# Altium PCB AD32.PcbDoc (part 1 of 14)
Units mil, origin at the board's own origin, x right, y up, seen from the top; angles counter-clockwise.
Board outline 7007.87 x 4368.85 mil, 12 copper layers (Top Layer, Int1 (GND), Int2 (AVDD), Int3 (DVDD), Int4 (GND), Int5 (ST), Int6 (SB), Int8 (AGND), Int7 (AVCC), Int9 (VCCA), Int10 (GND), Bottom Layer), stack 60.136 mil thick; 1350 components, 880 nets, 4712 pads, 2835 vias.
Unrouted connection lines stored in the file: 19.
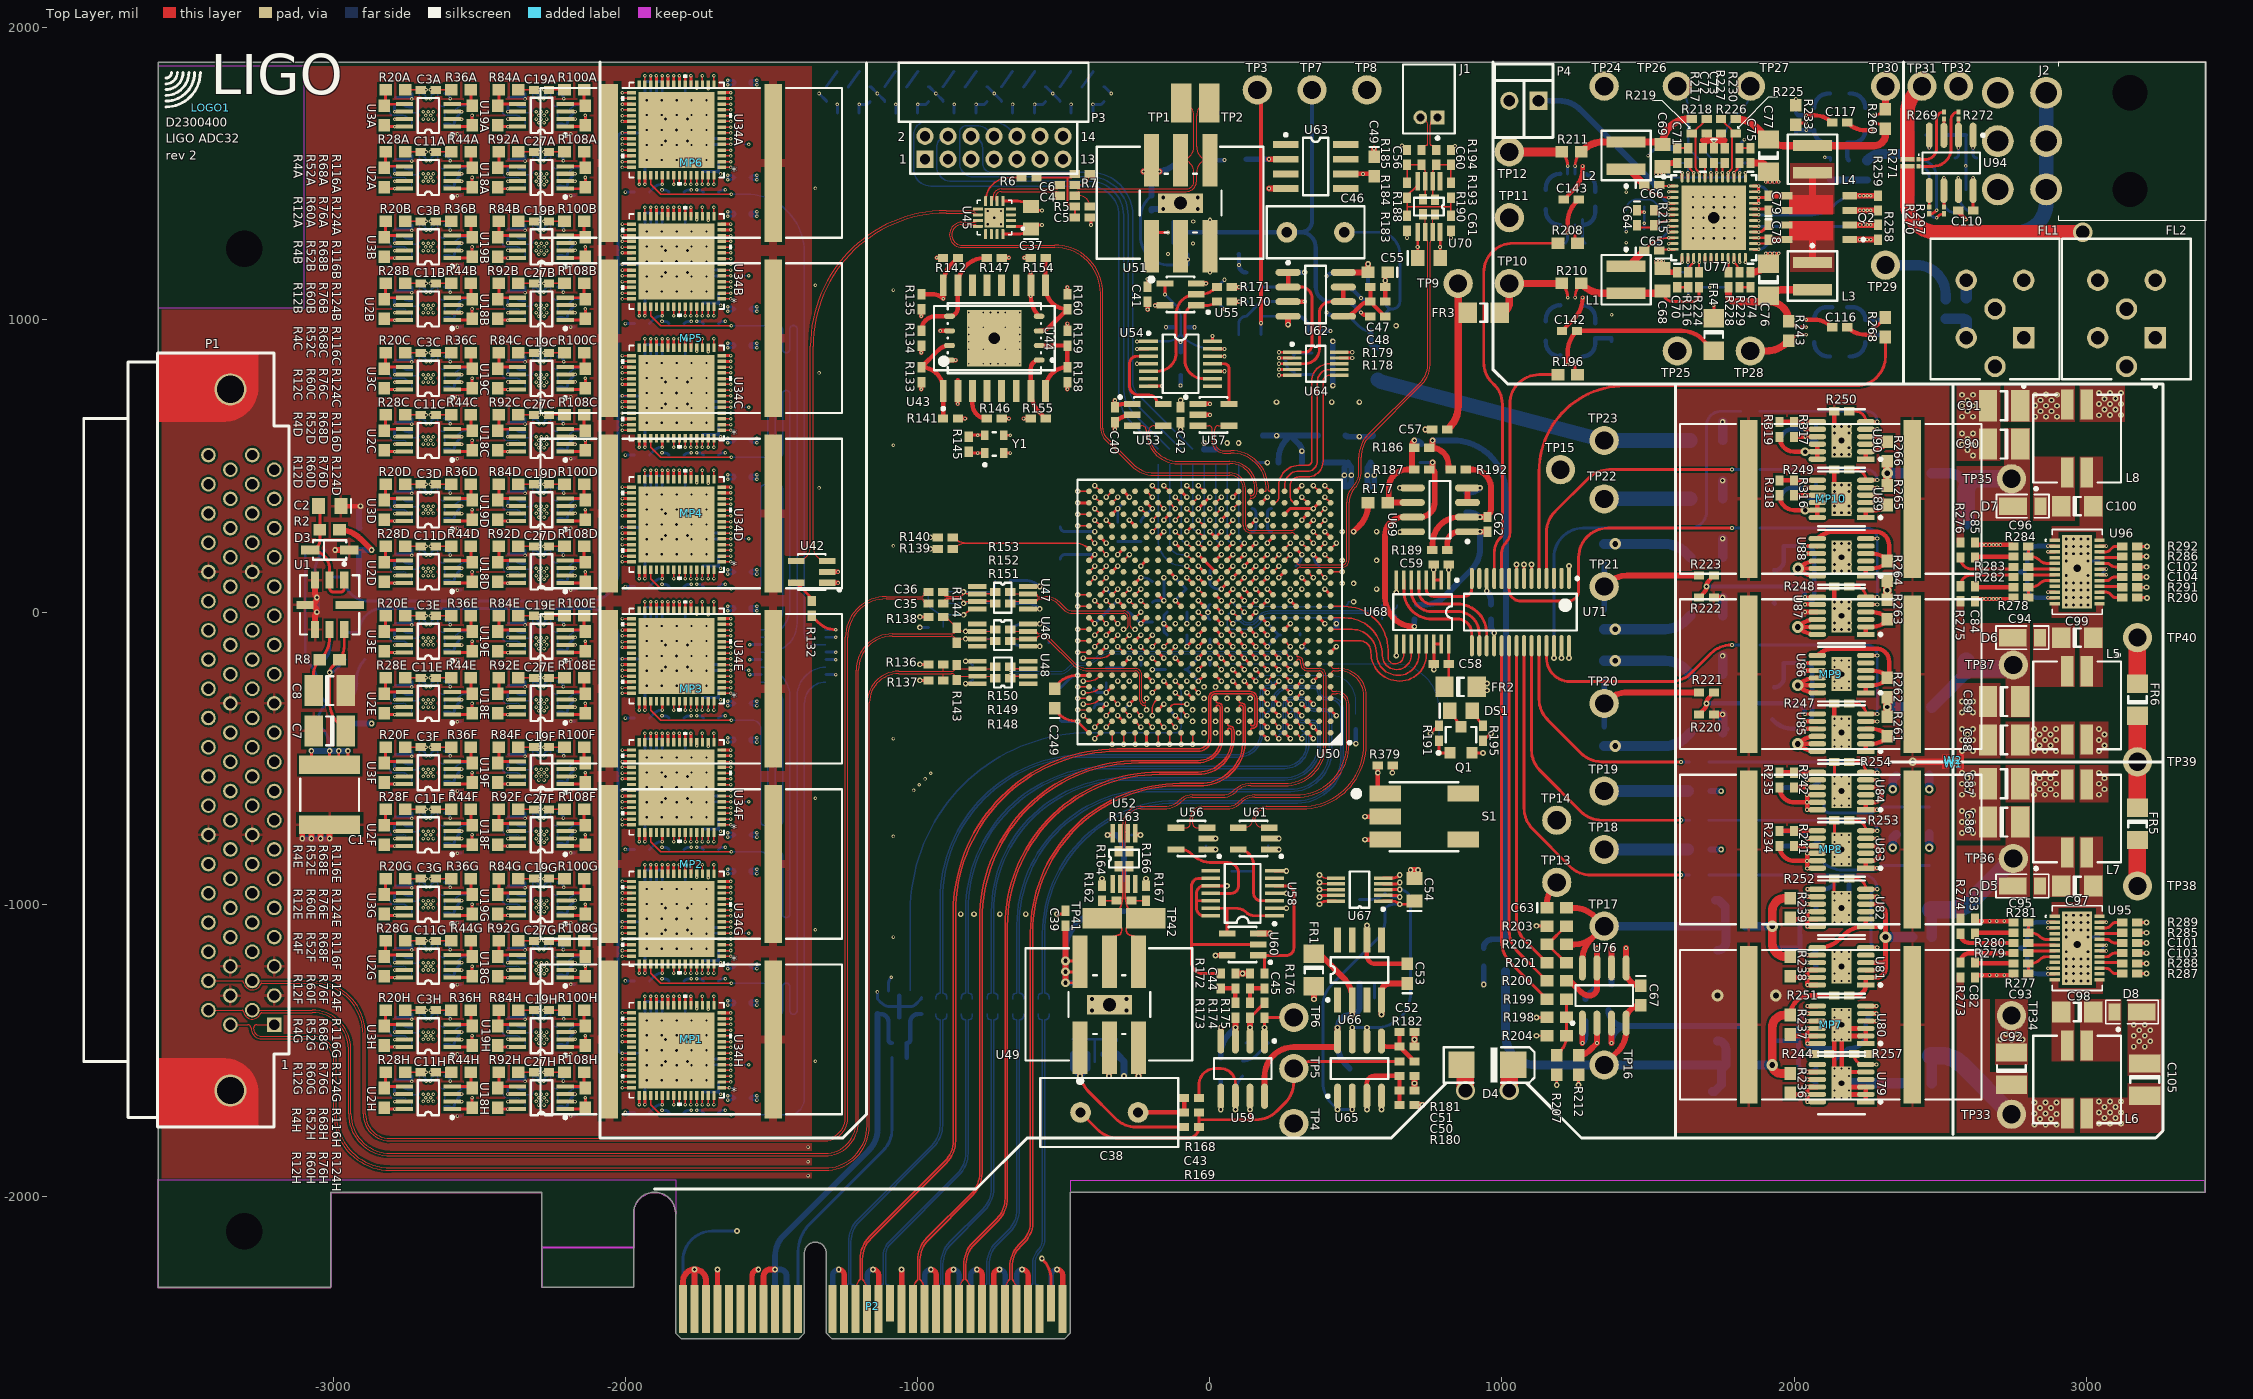
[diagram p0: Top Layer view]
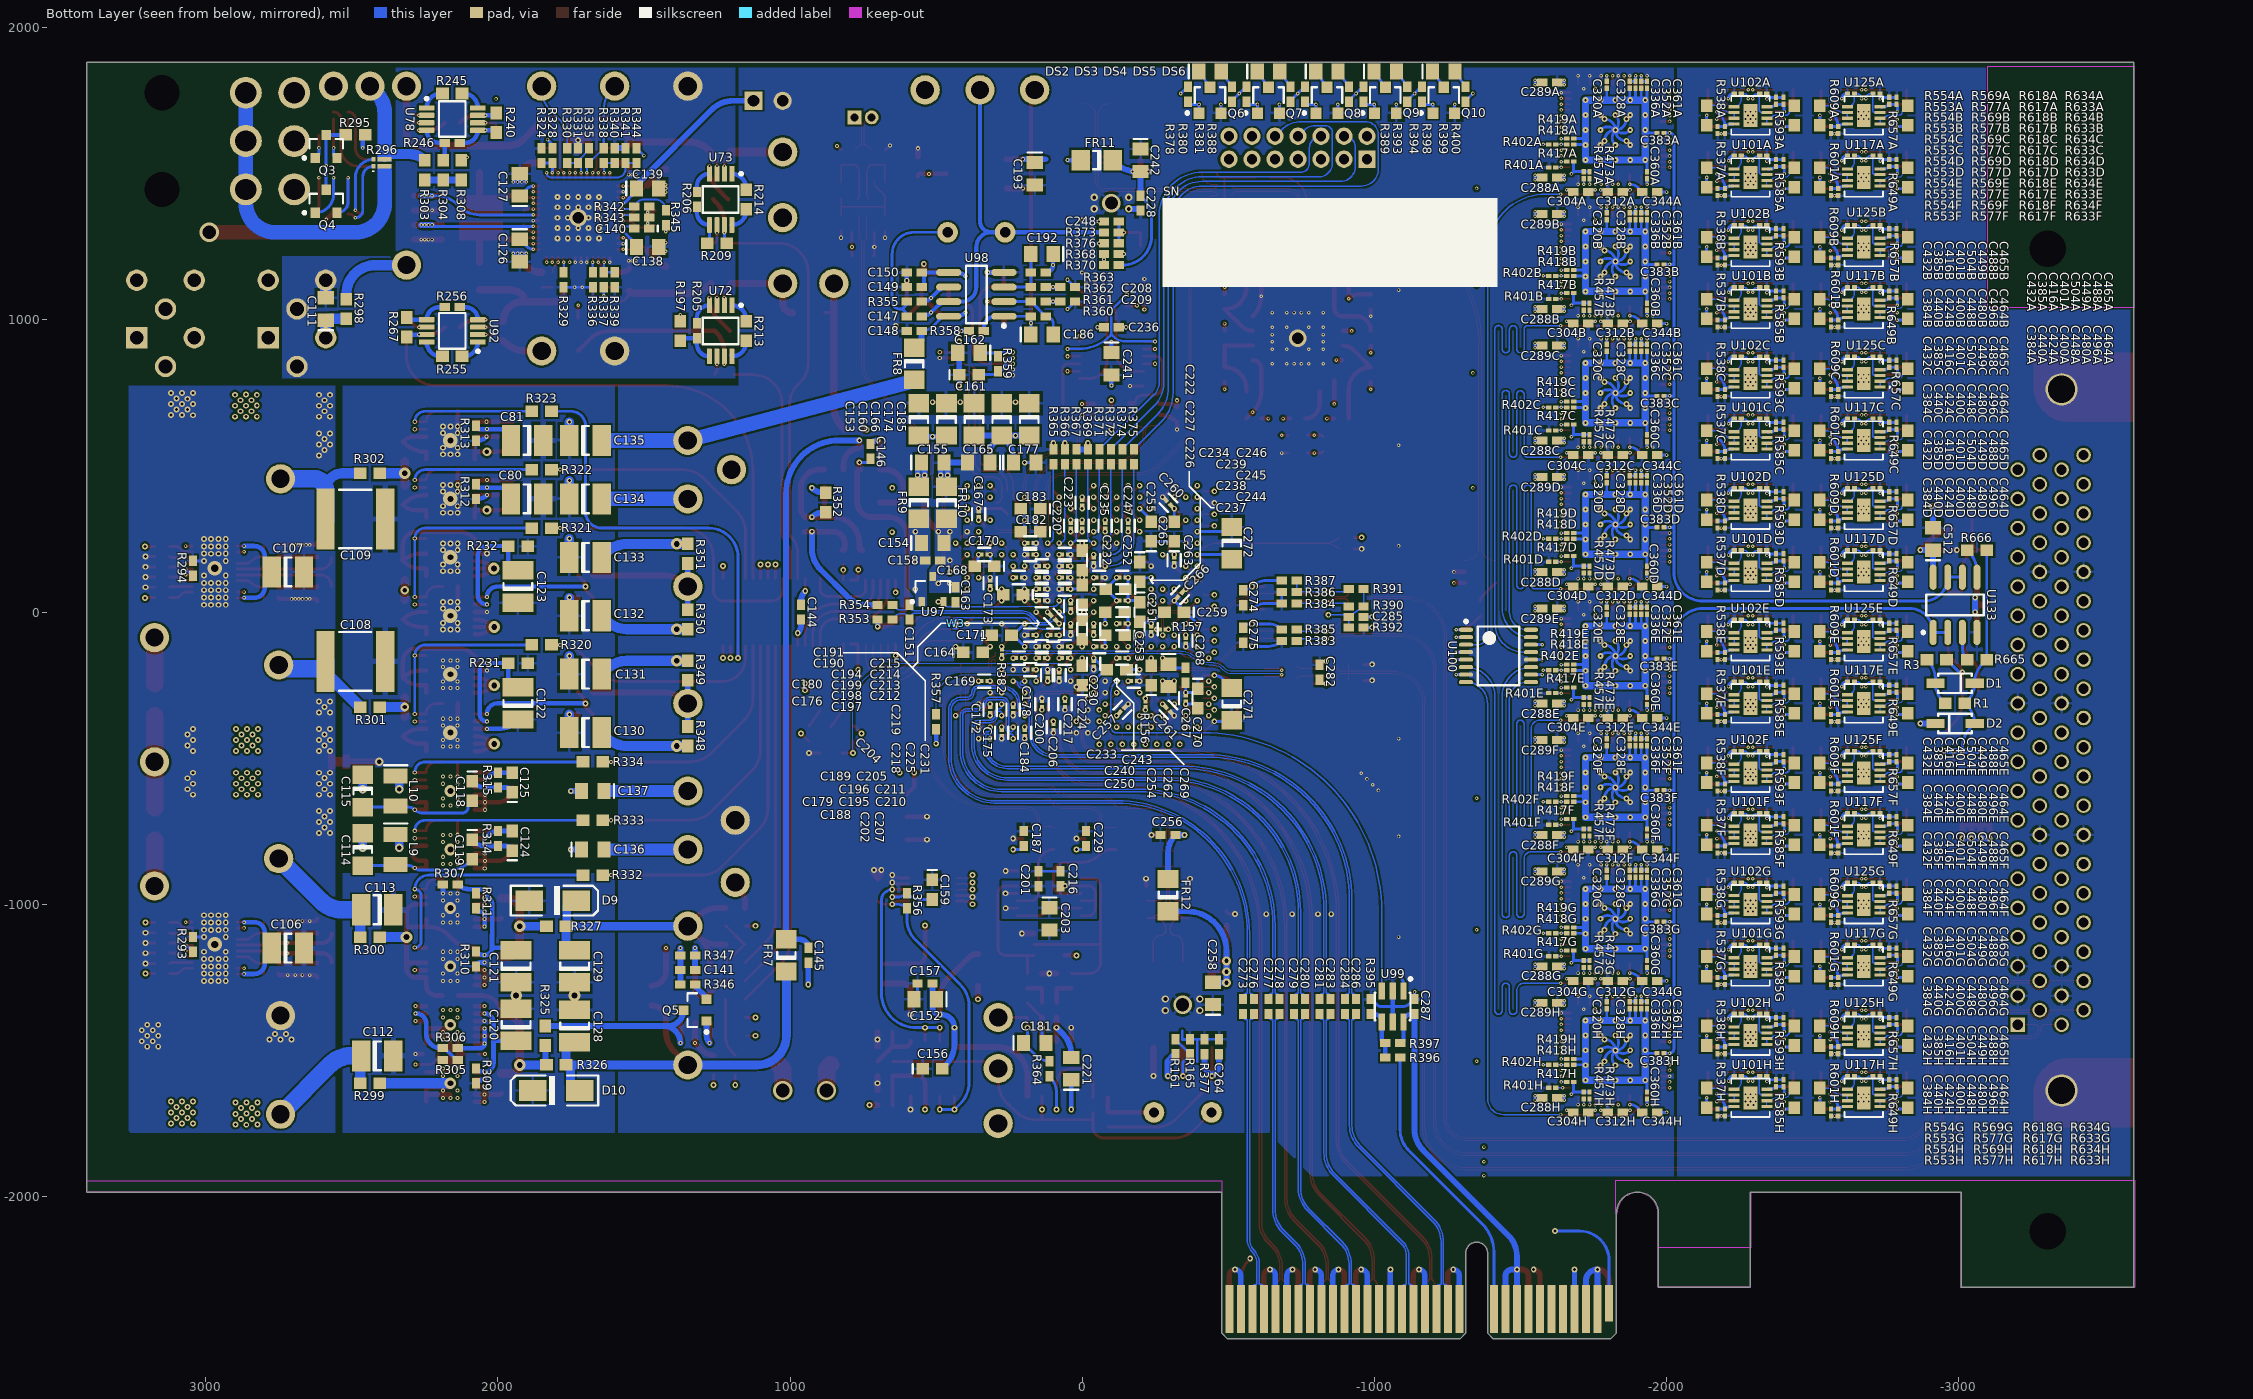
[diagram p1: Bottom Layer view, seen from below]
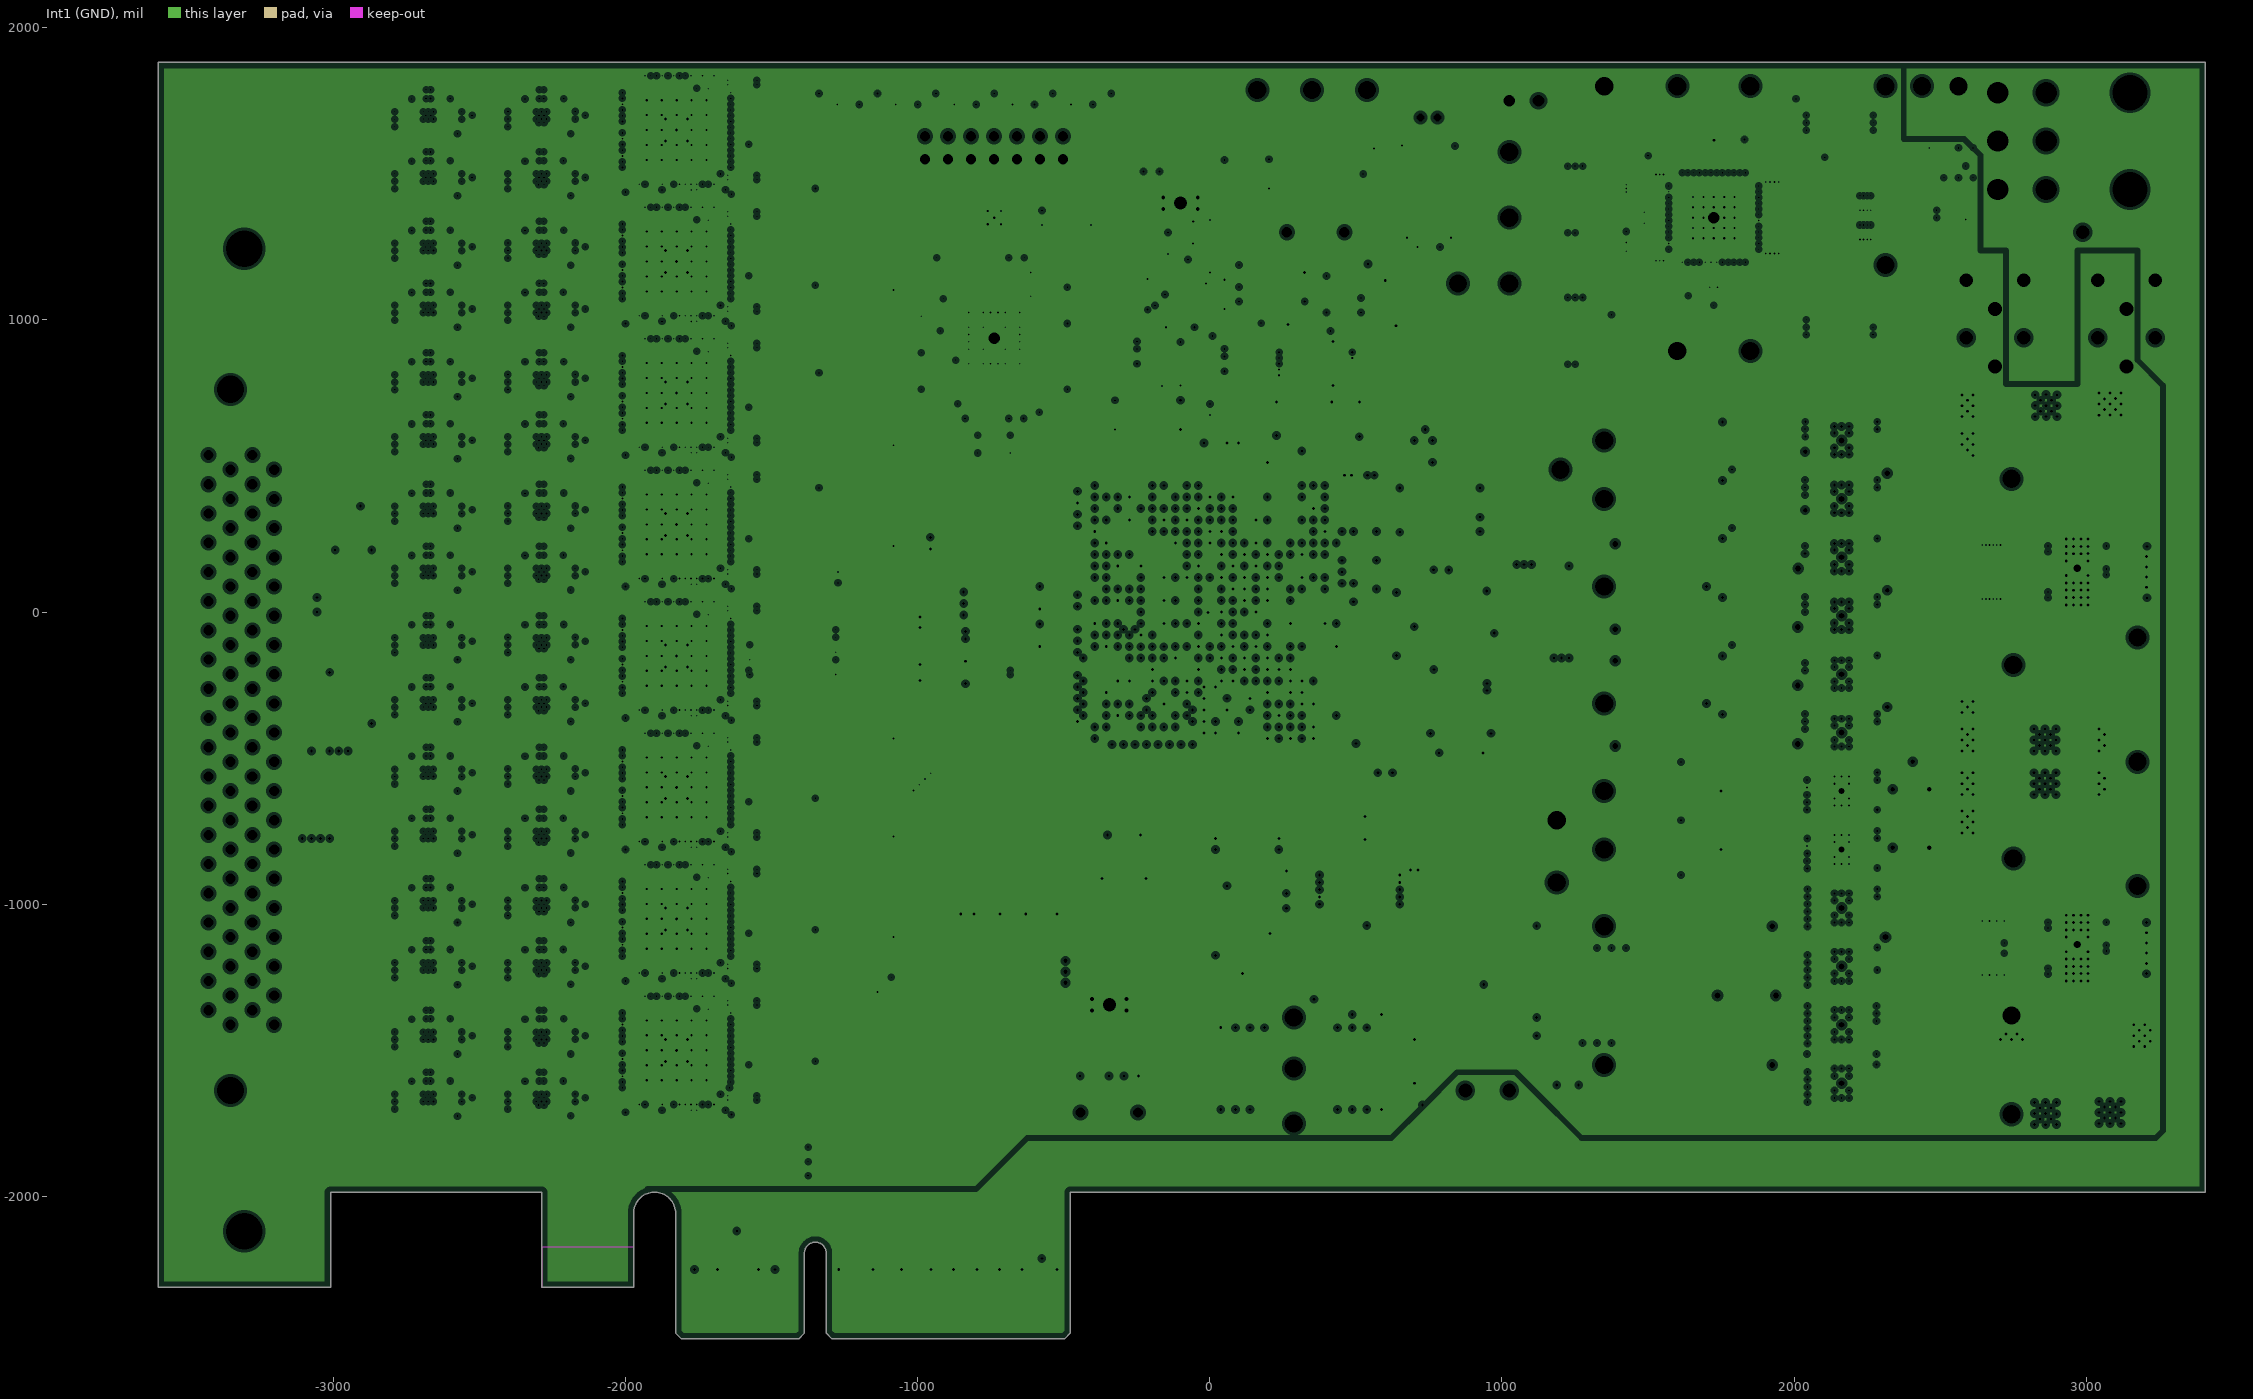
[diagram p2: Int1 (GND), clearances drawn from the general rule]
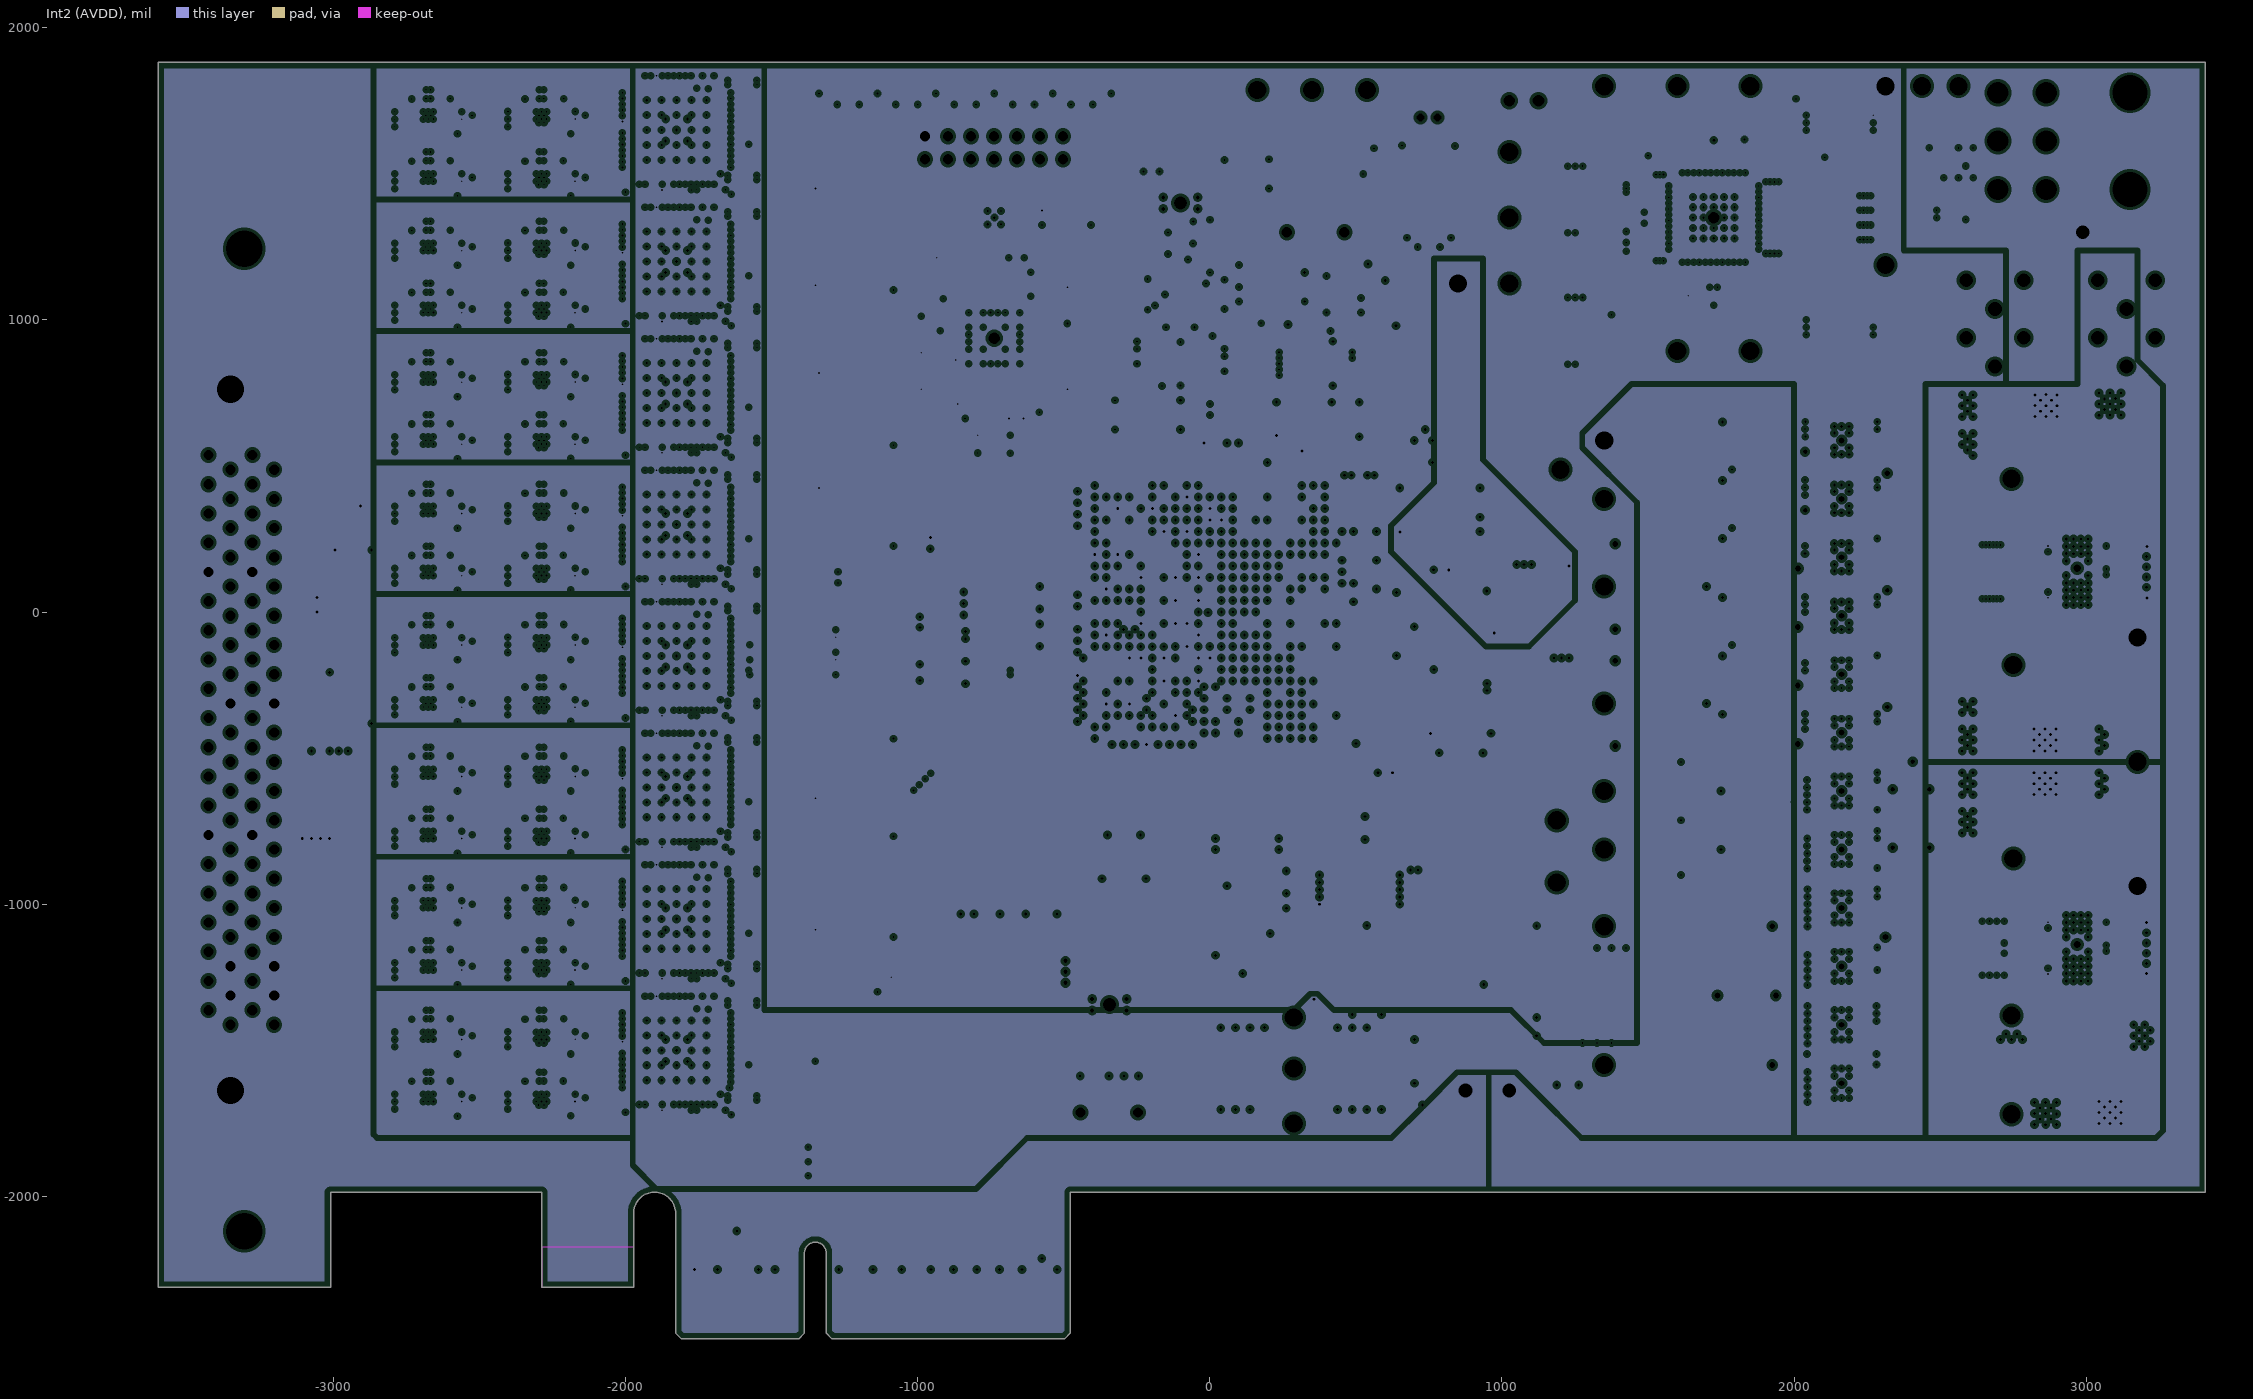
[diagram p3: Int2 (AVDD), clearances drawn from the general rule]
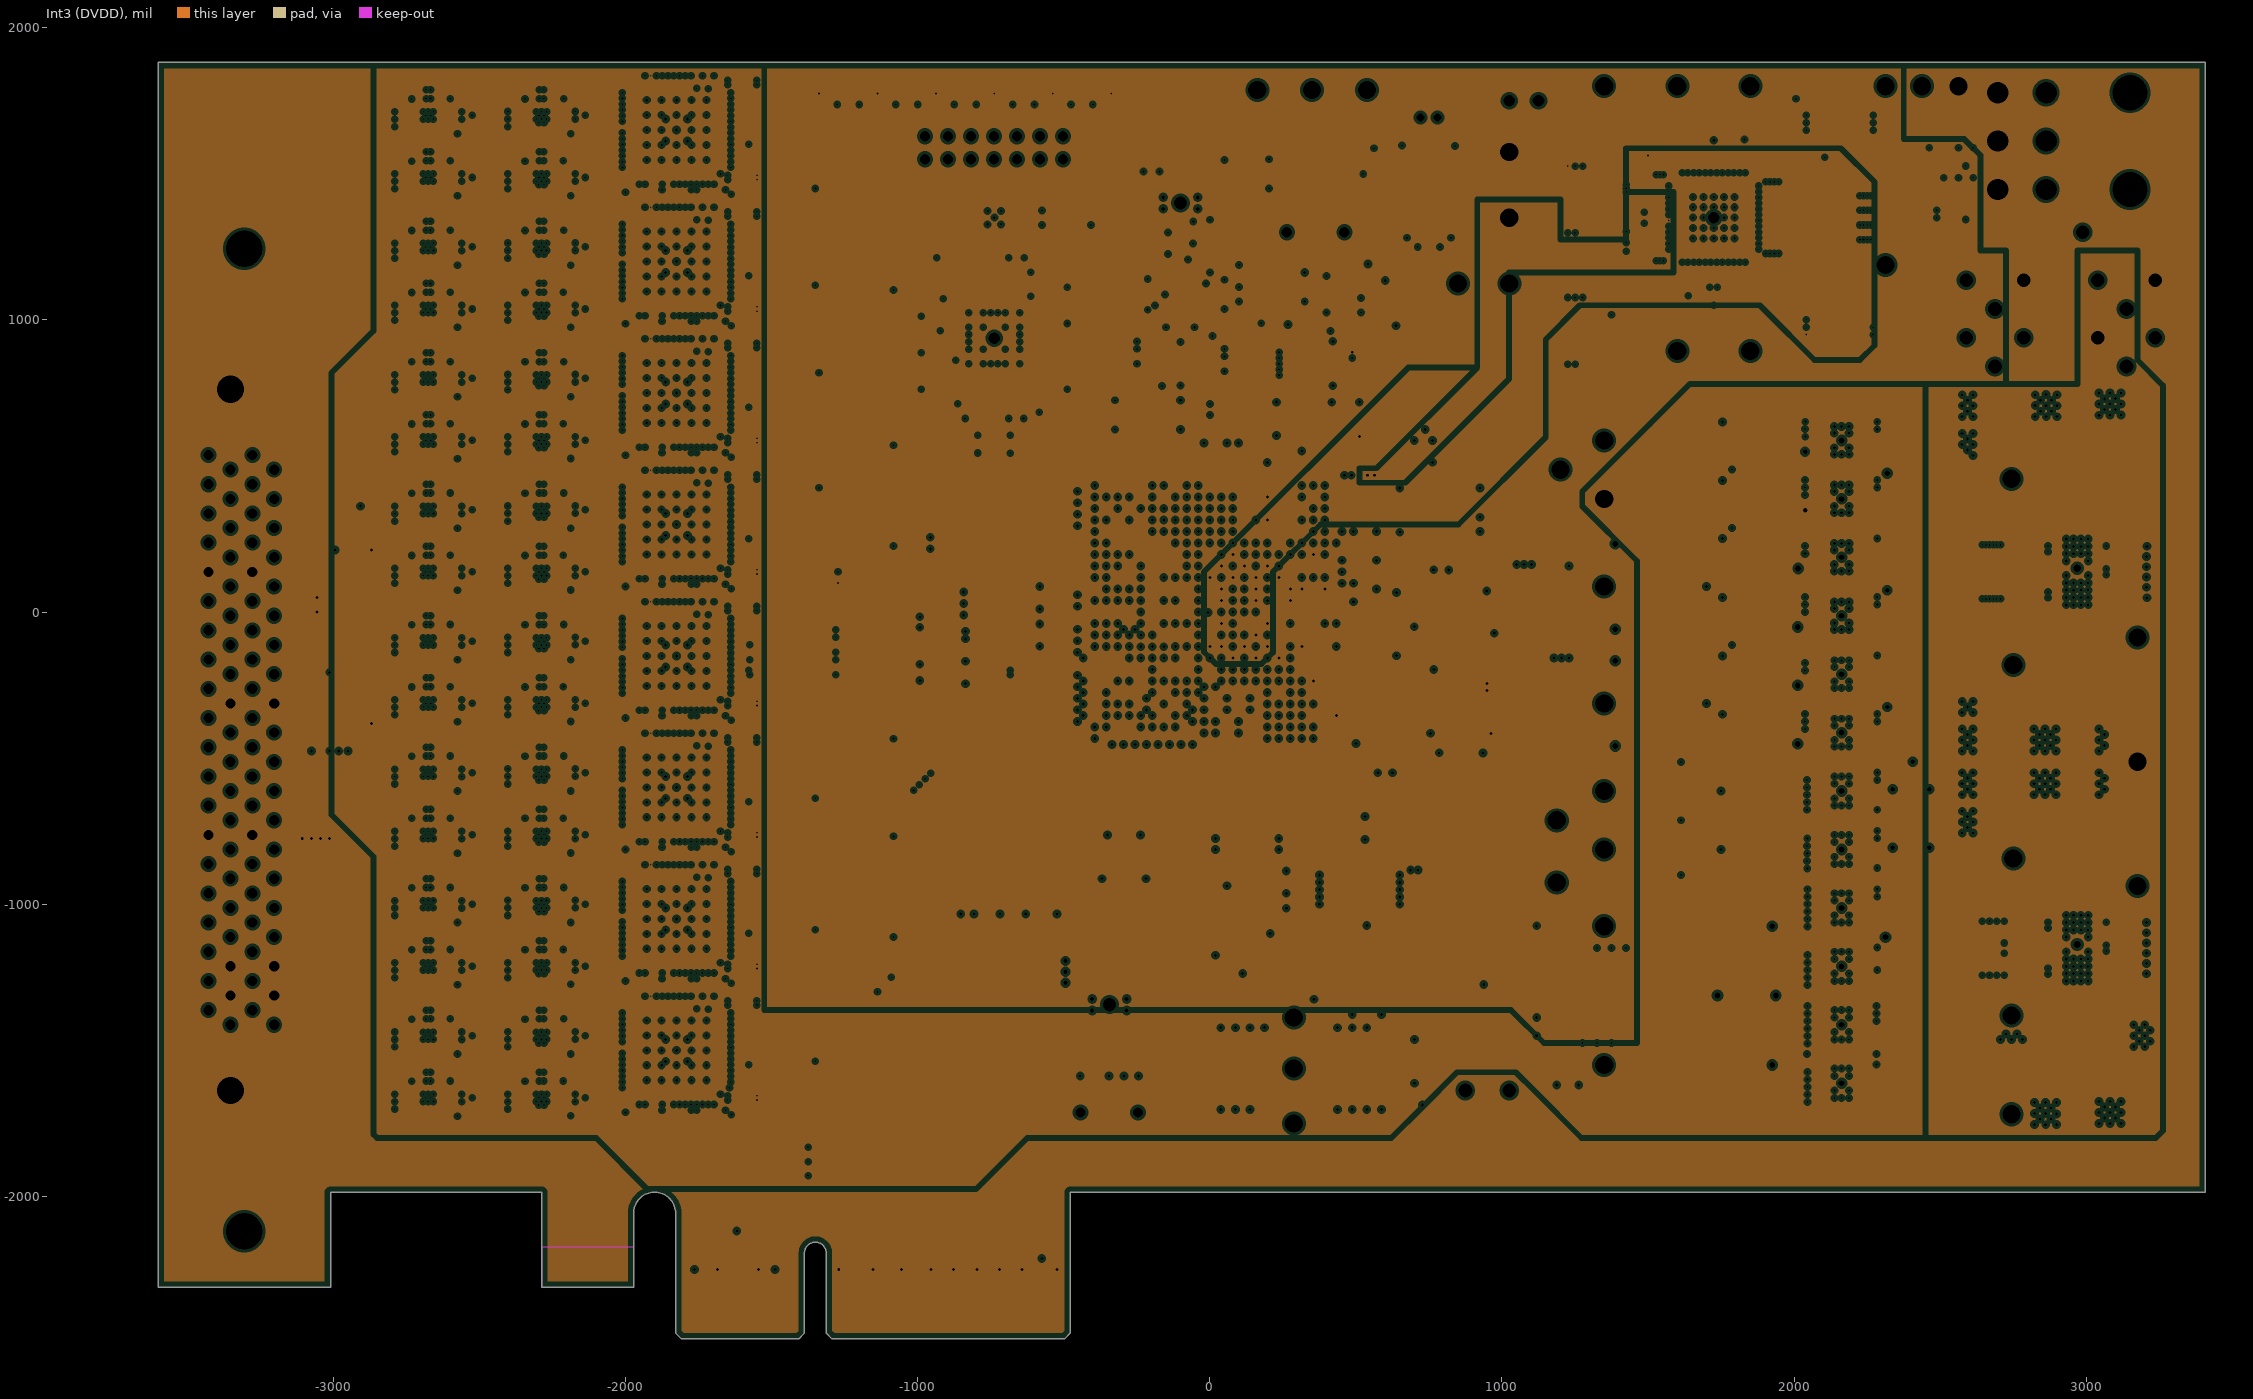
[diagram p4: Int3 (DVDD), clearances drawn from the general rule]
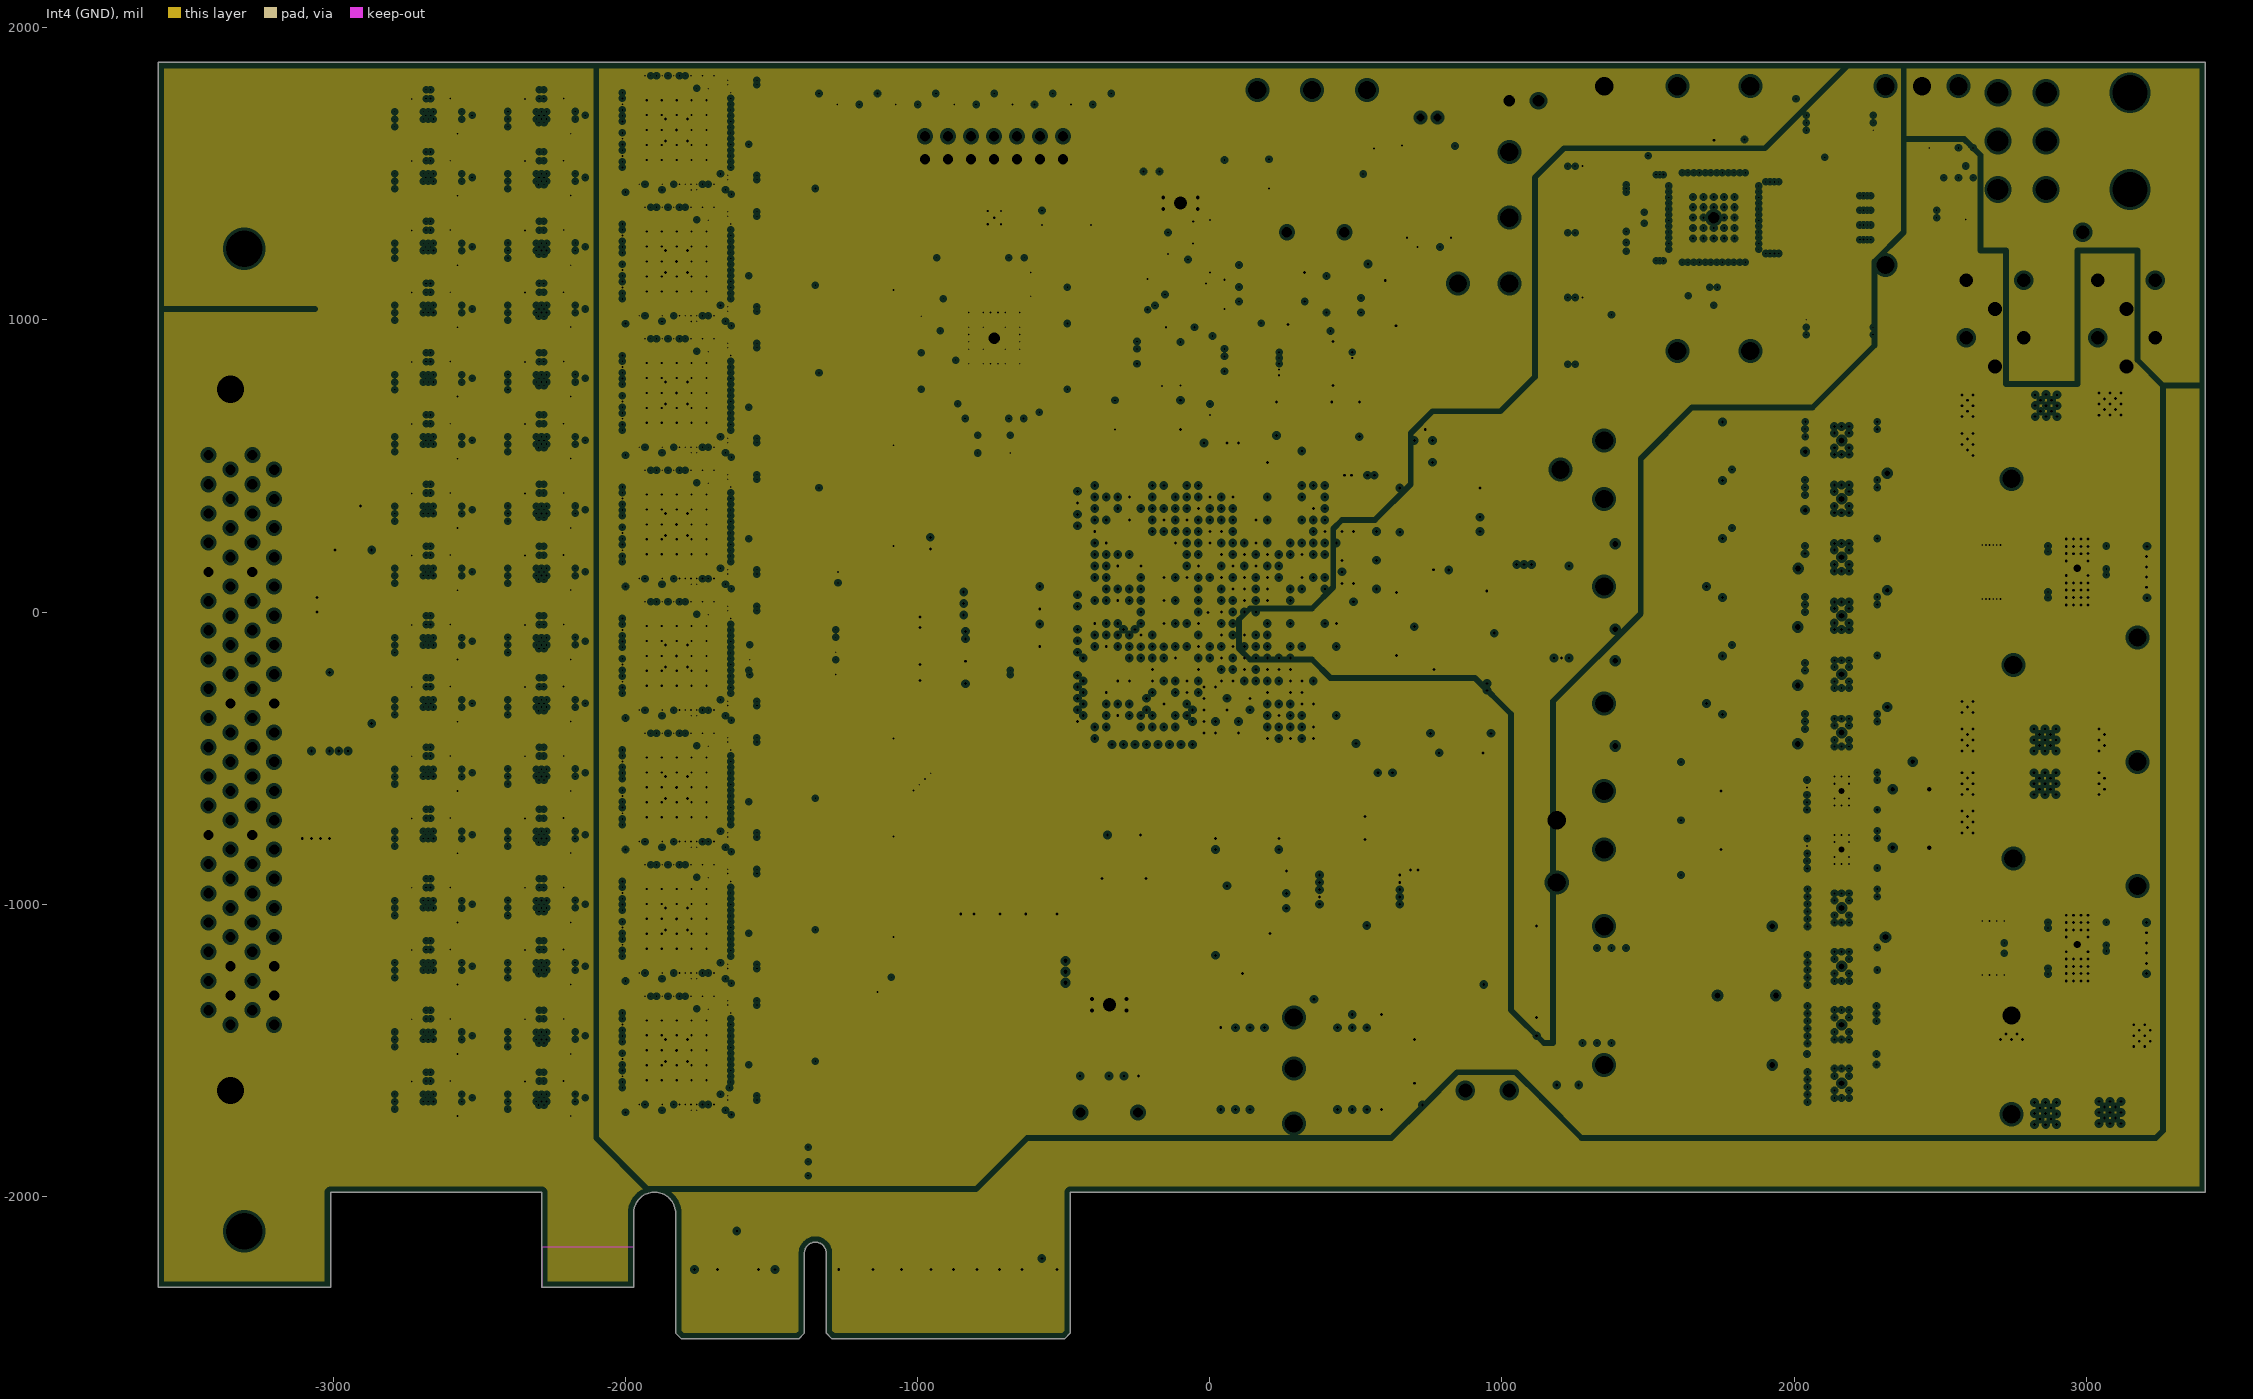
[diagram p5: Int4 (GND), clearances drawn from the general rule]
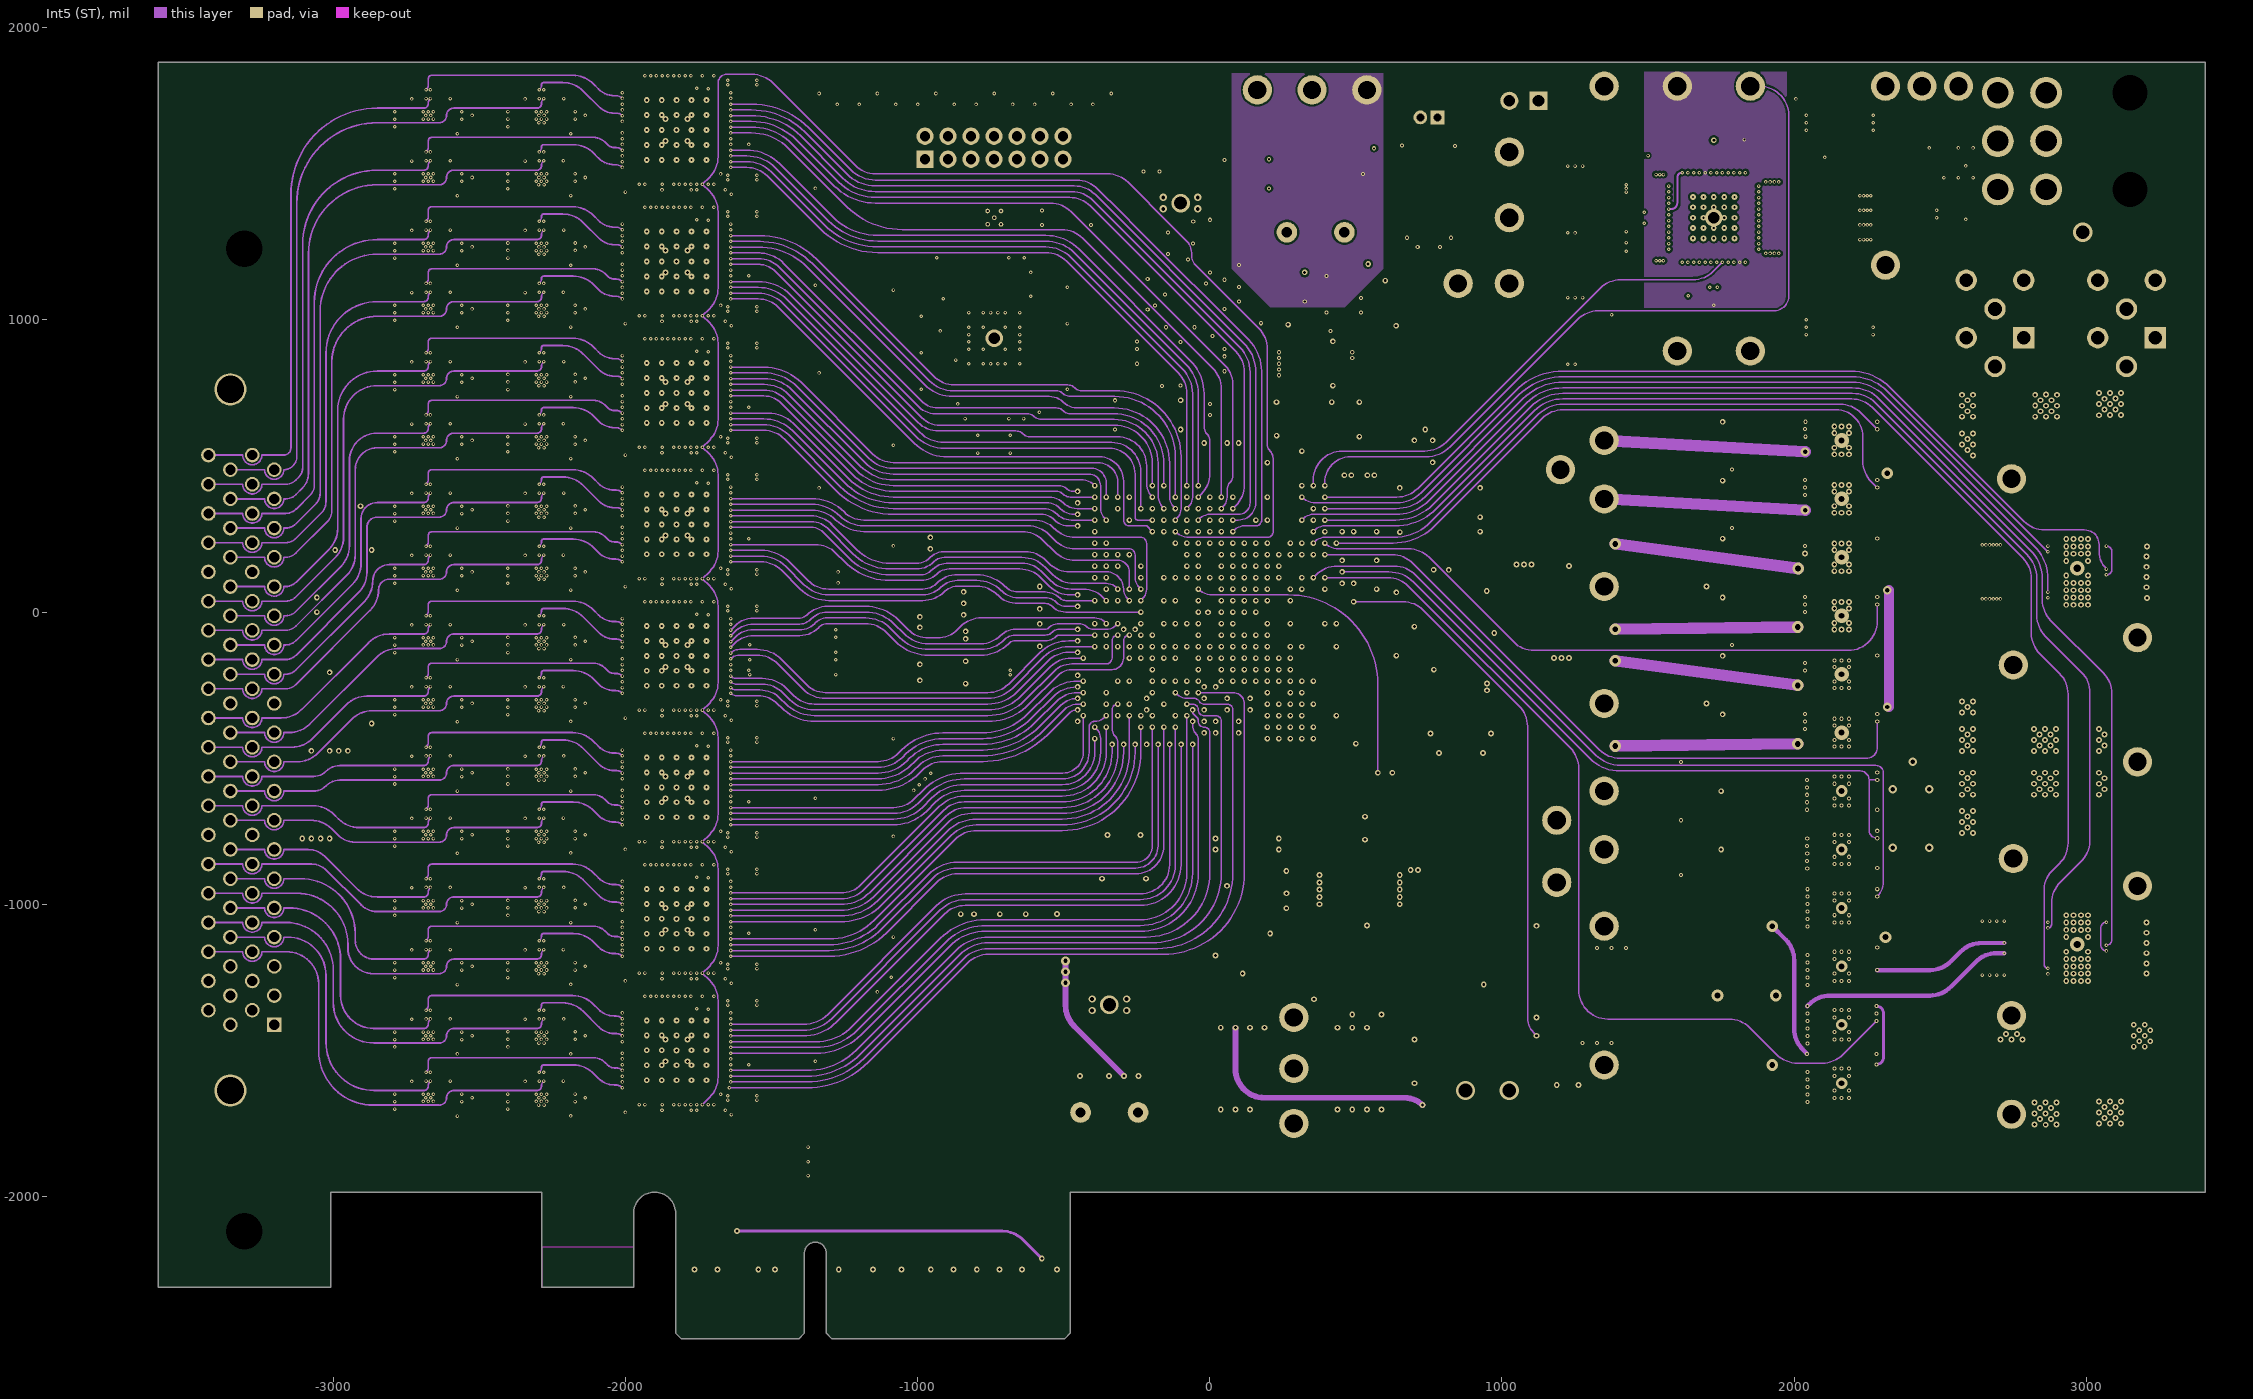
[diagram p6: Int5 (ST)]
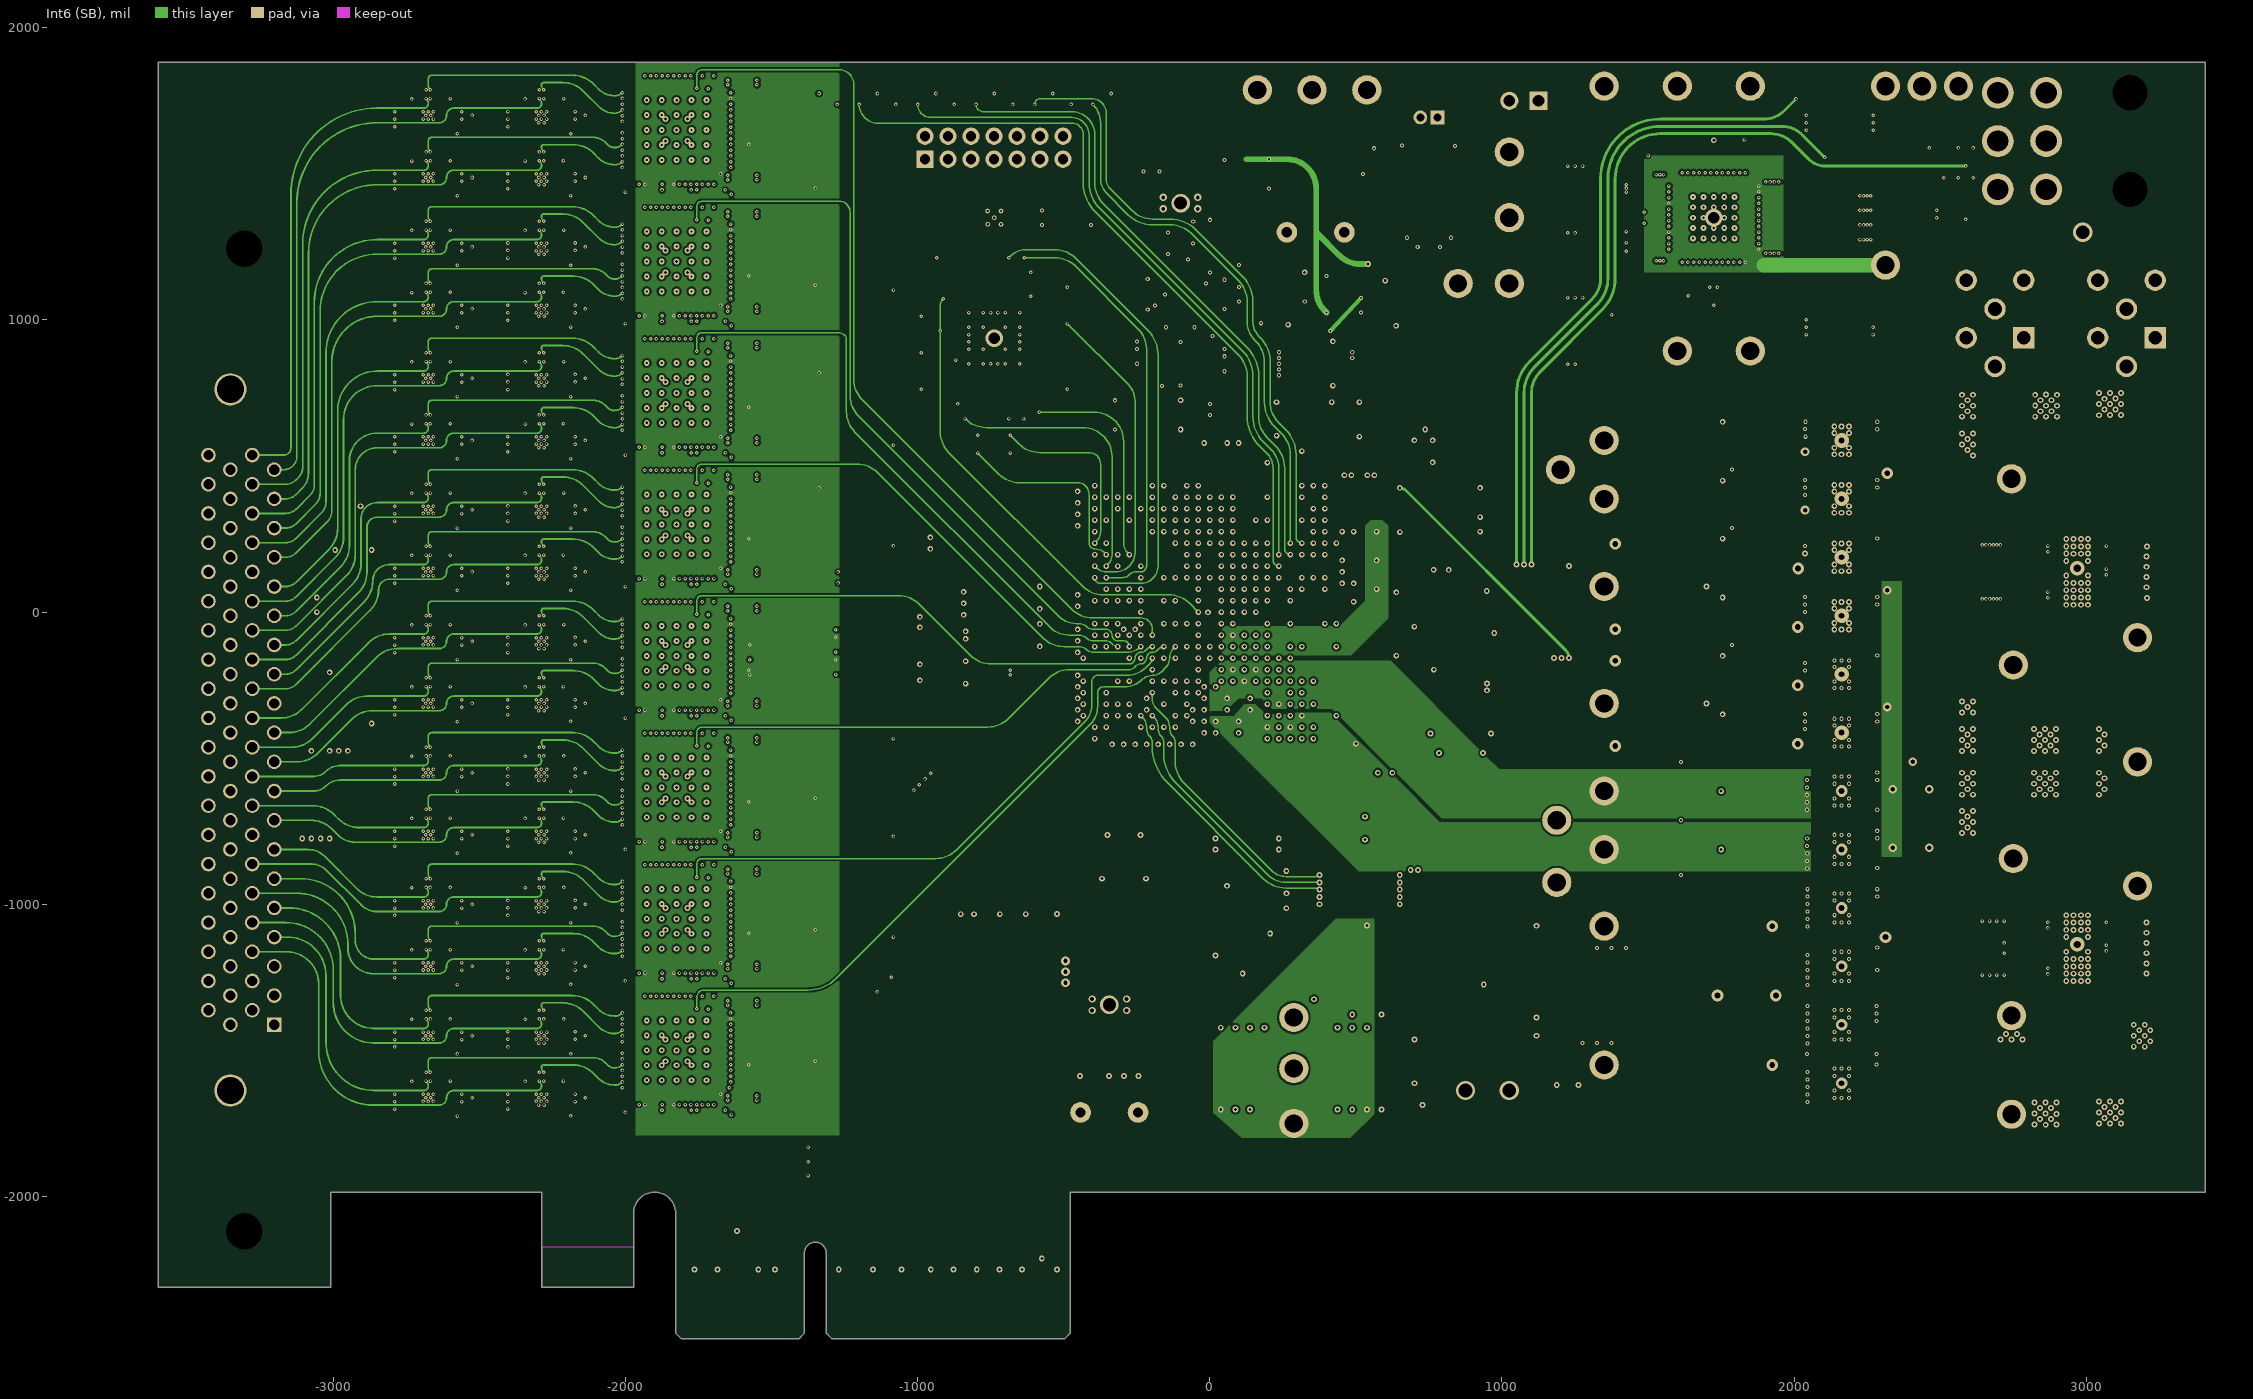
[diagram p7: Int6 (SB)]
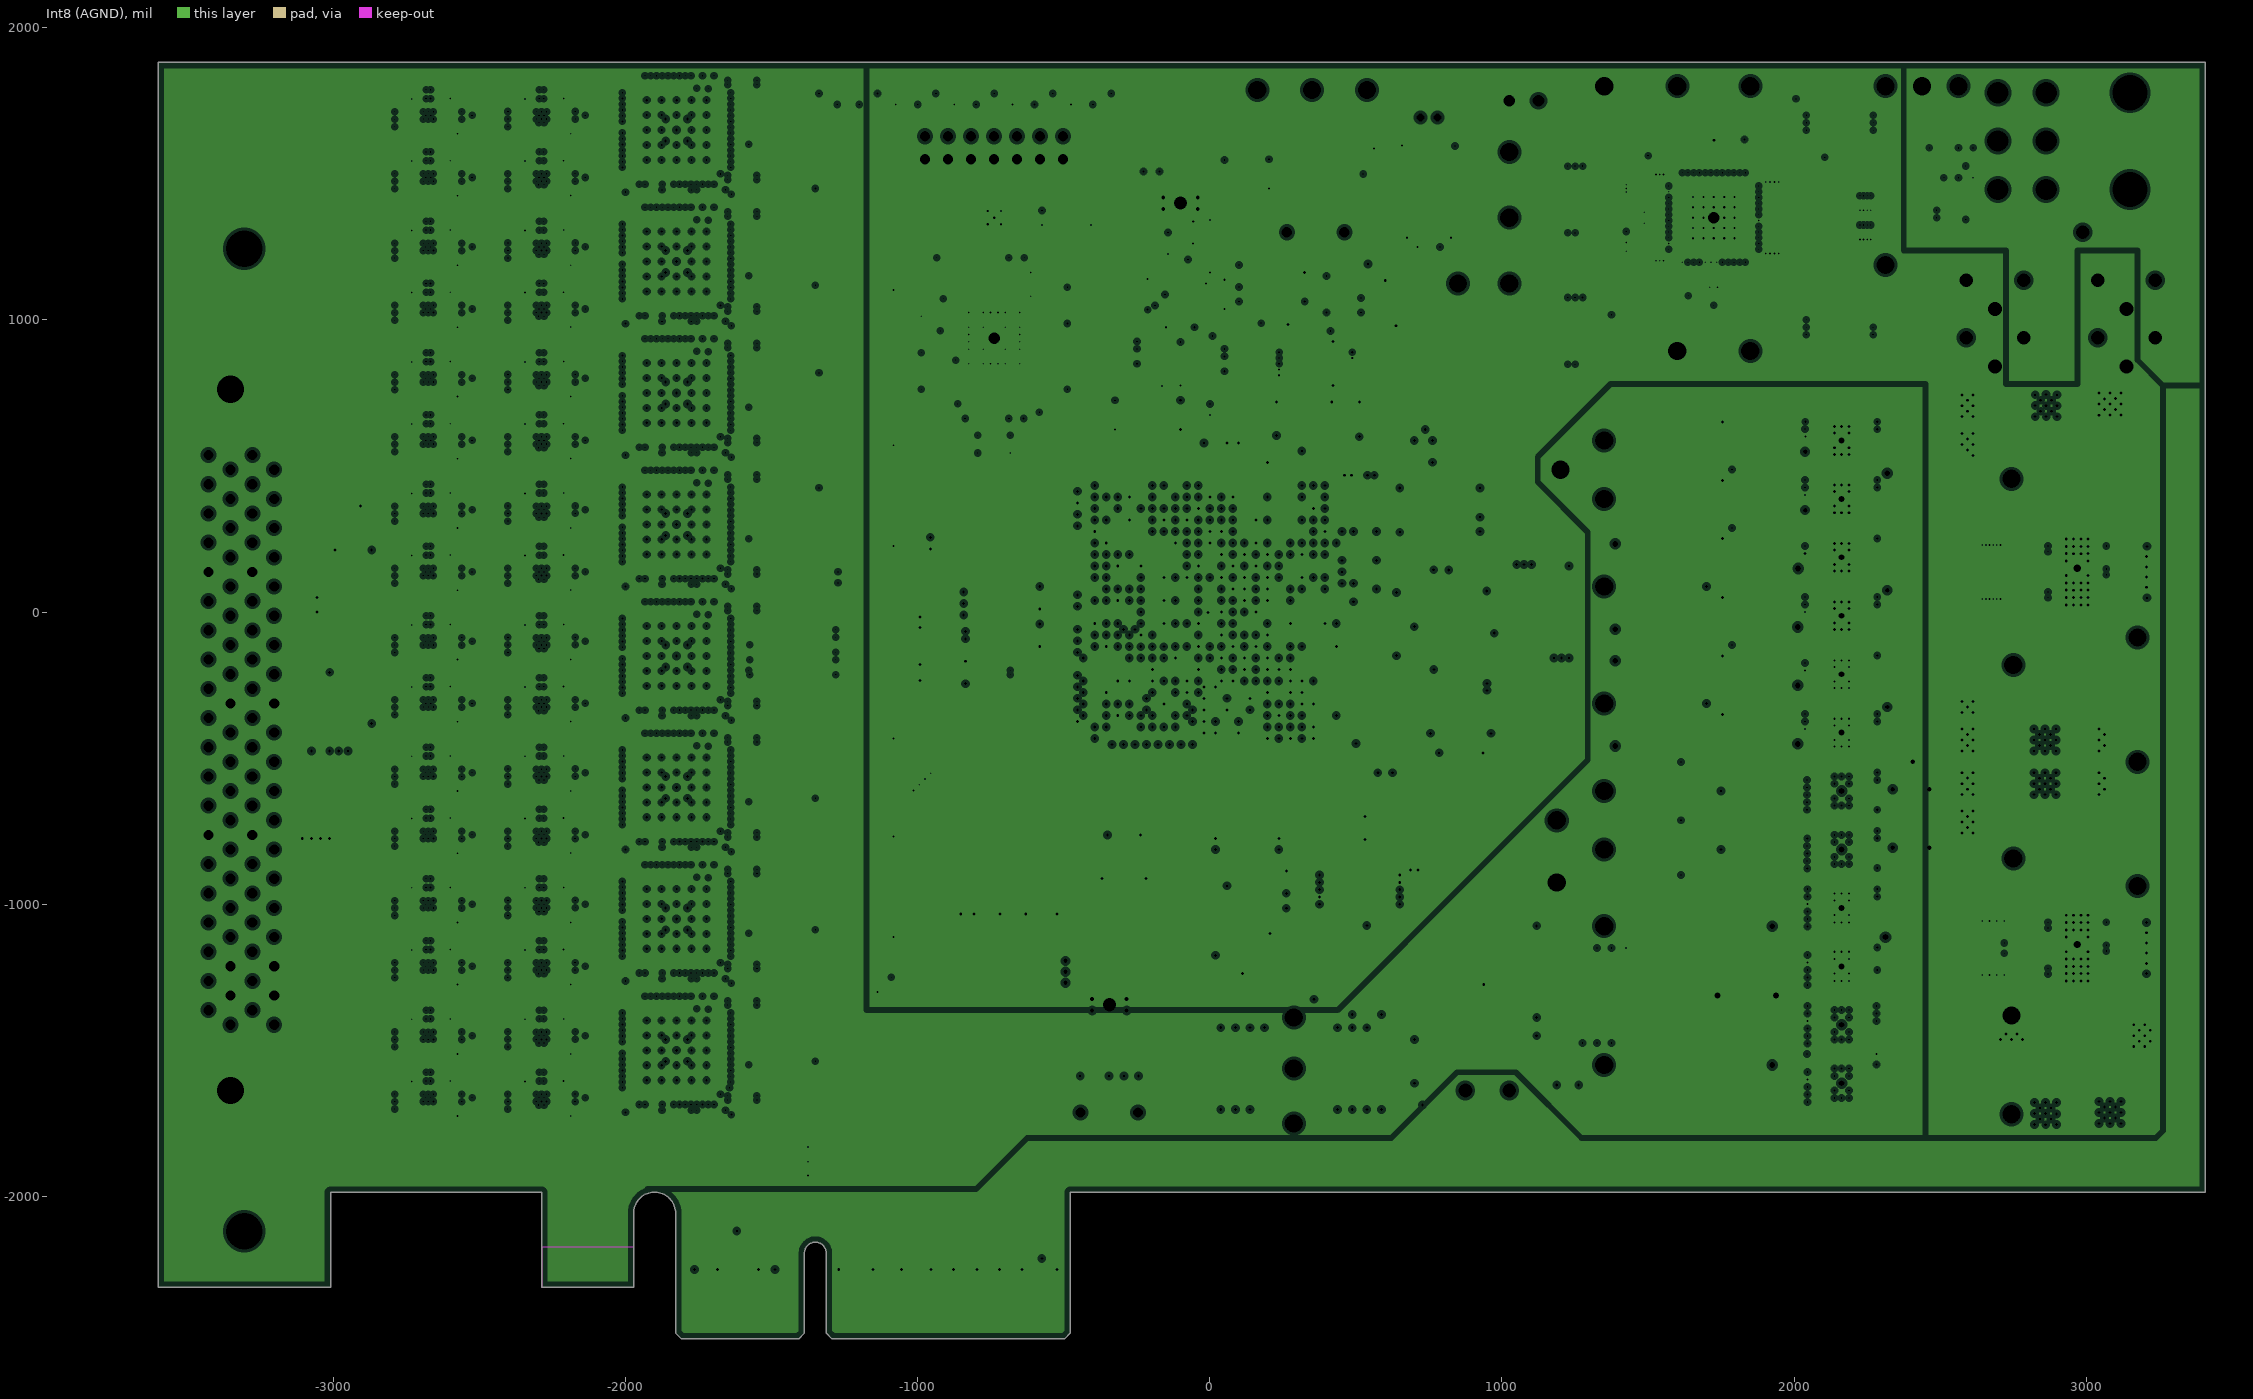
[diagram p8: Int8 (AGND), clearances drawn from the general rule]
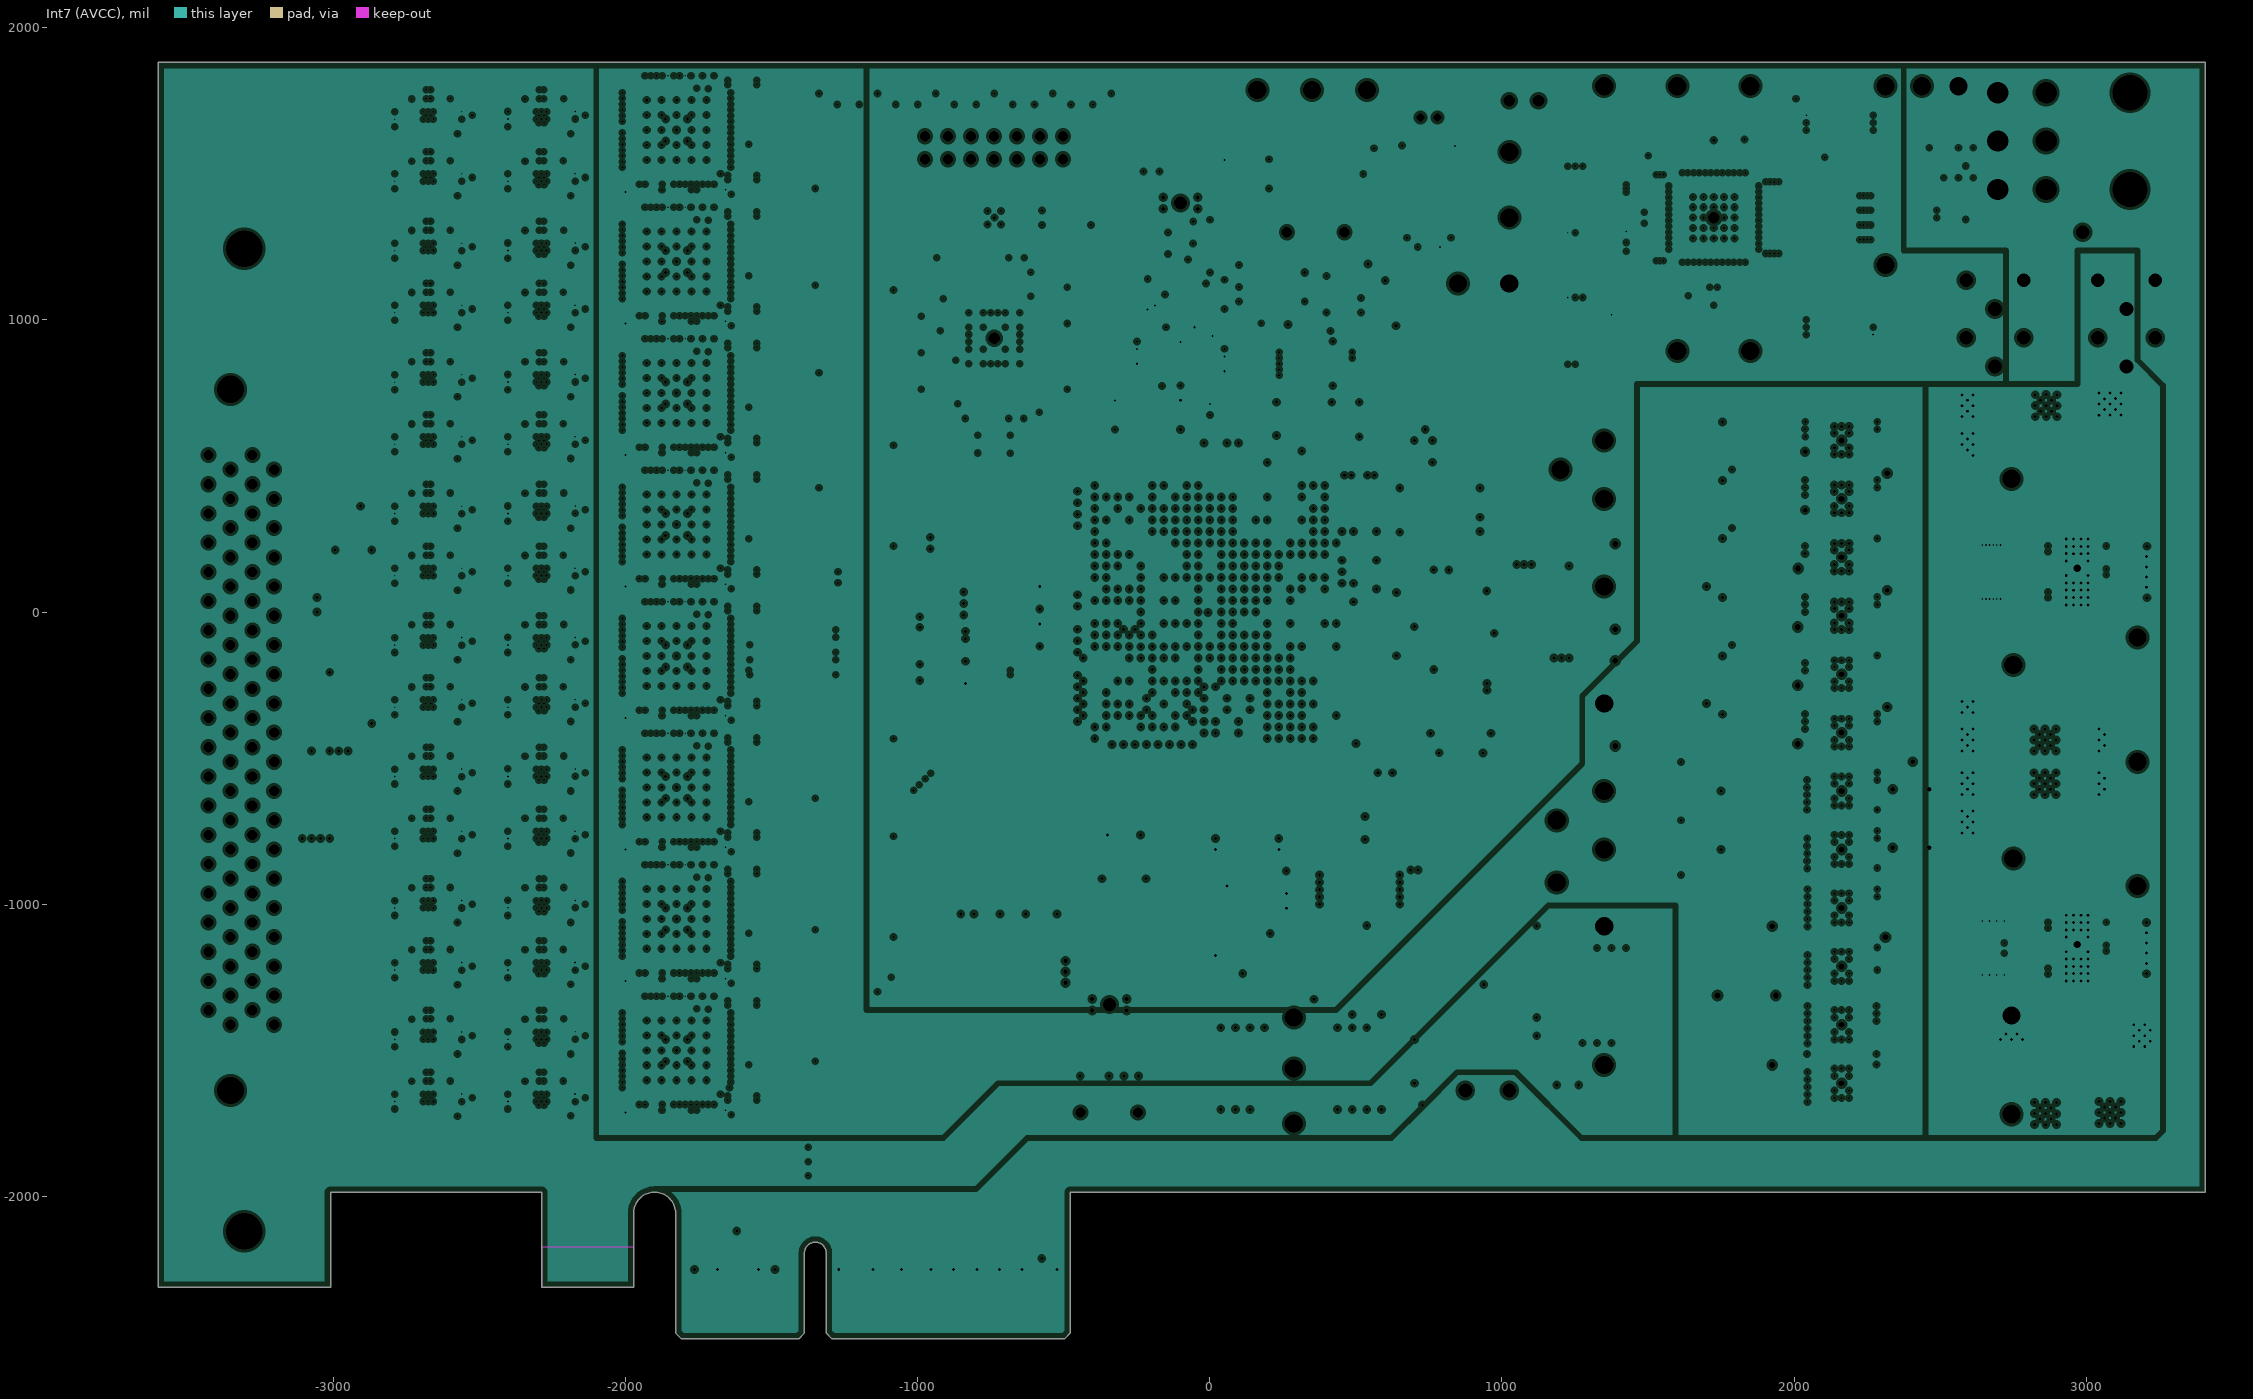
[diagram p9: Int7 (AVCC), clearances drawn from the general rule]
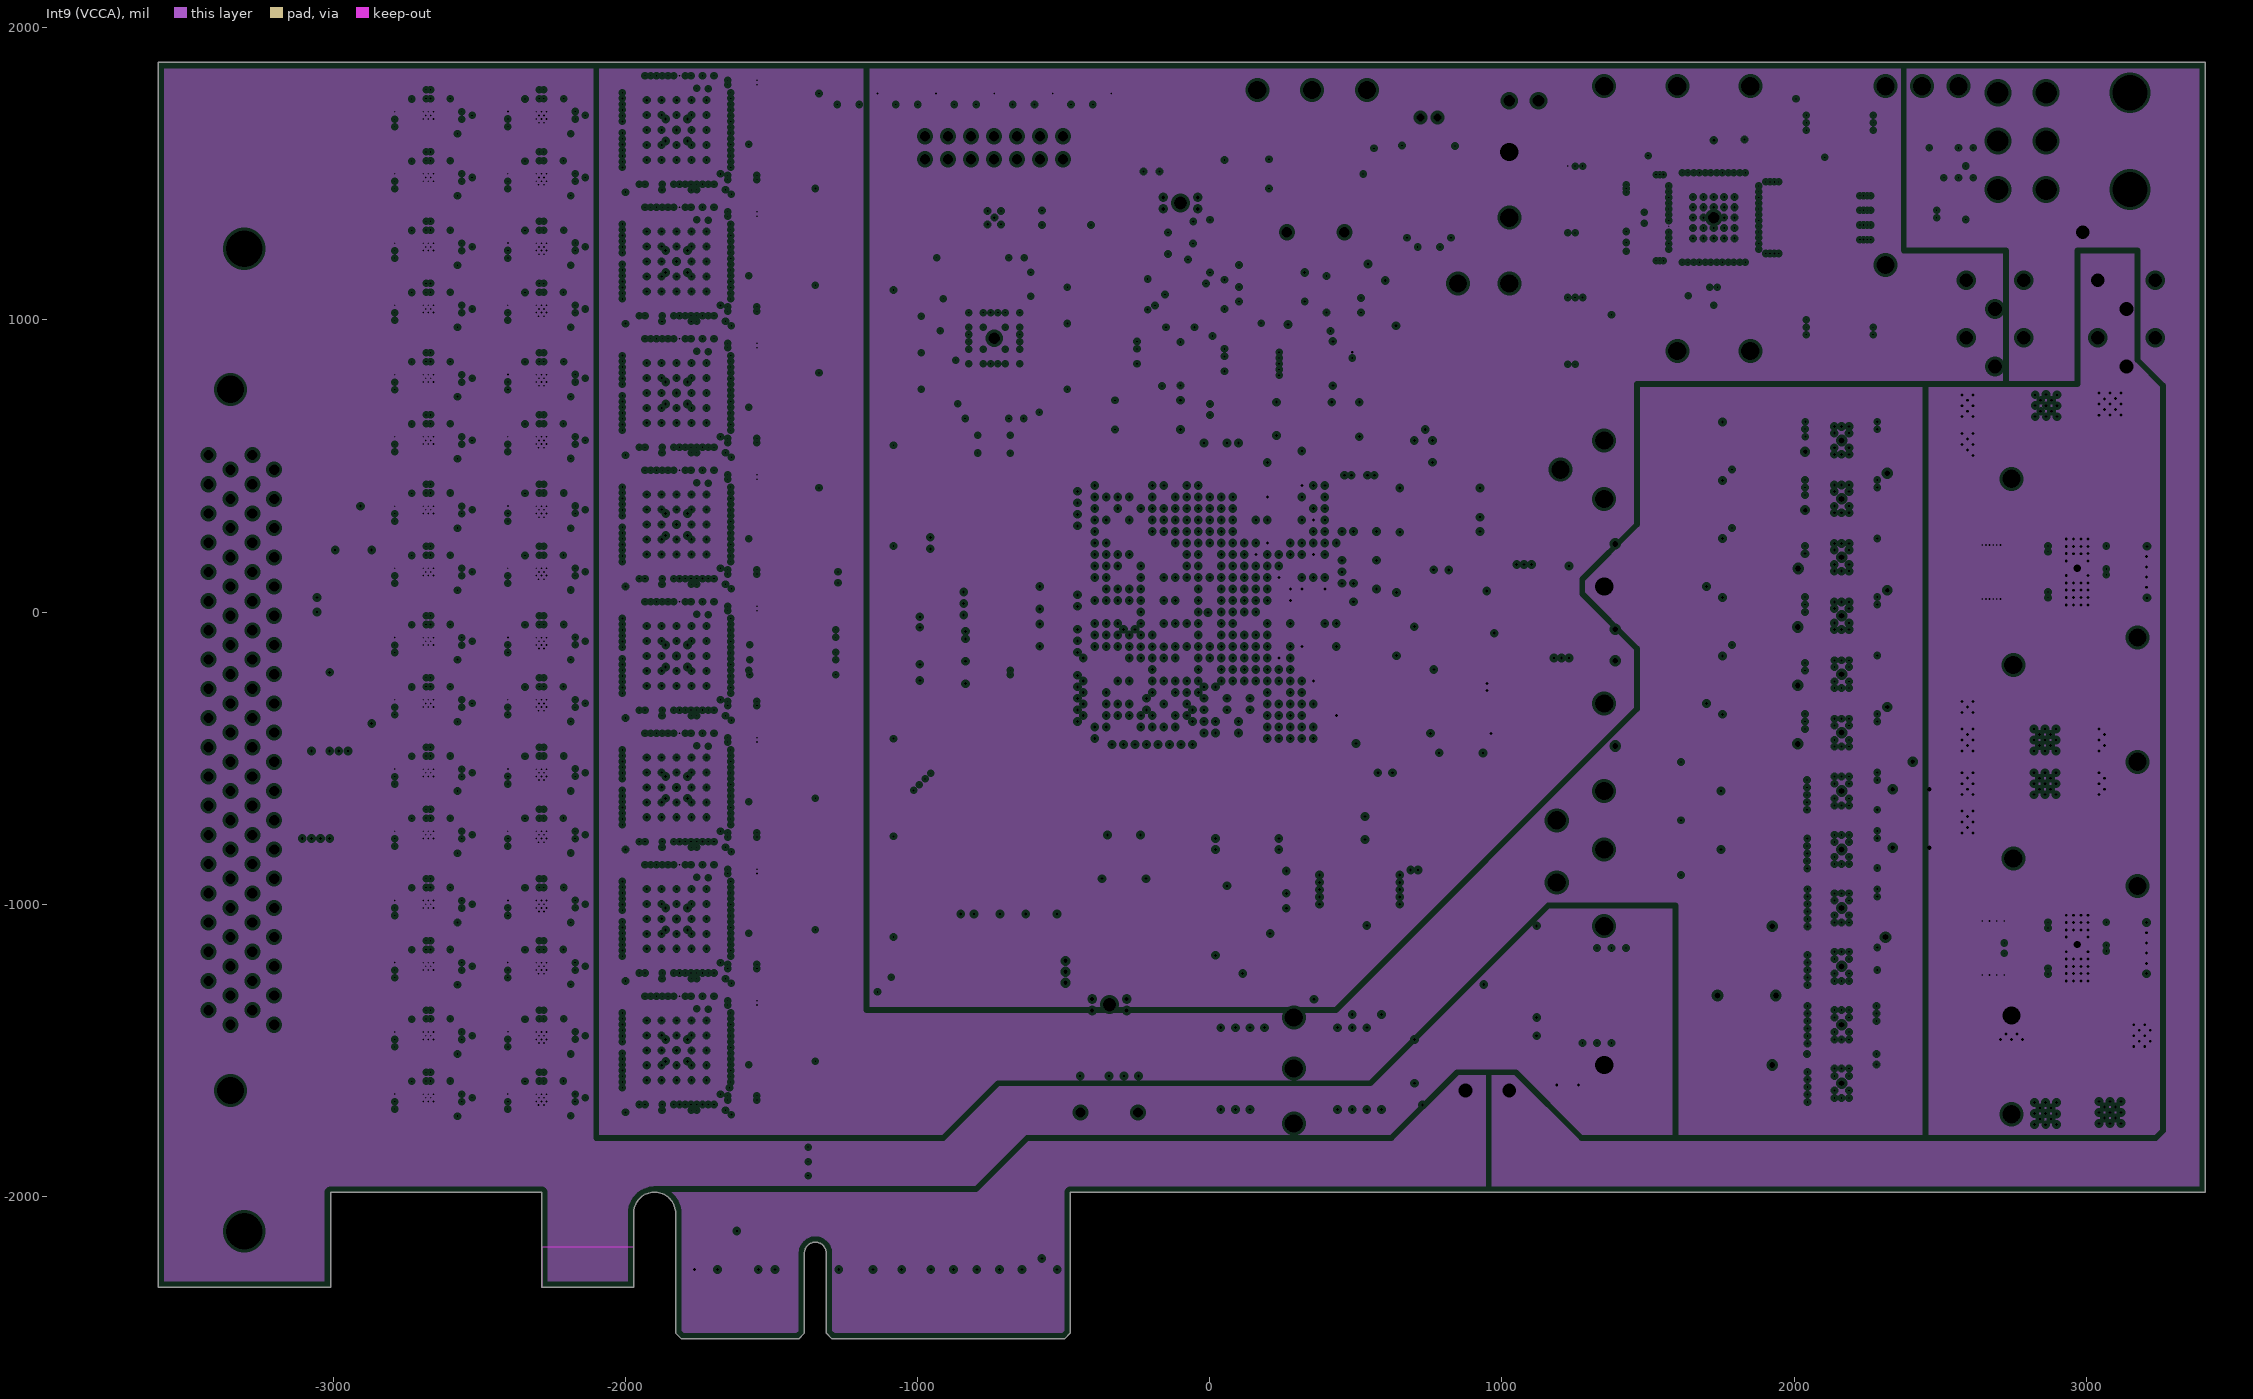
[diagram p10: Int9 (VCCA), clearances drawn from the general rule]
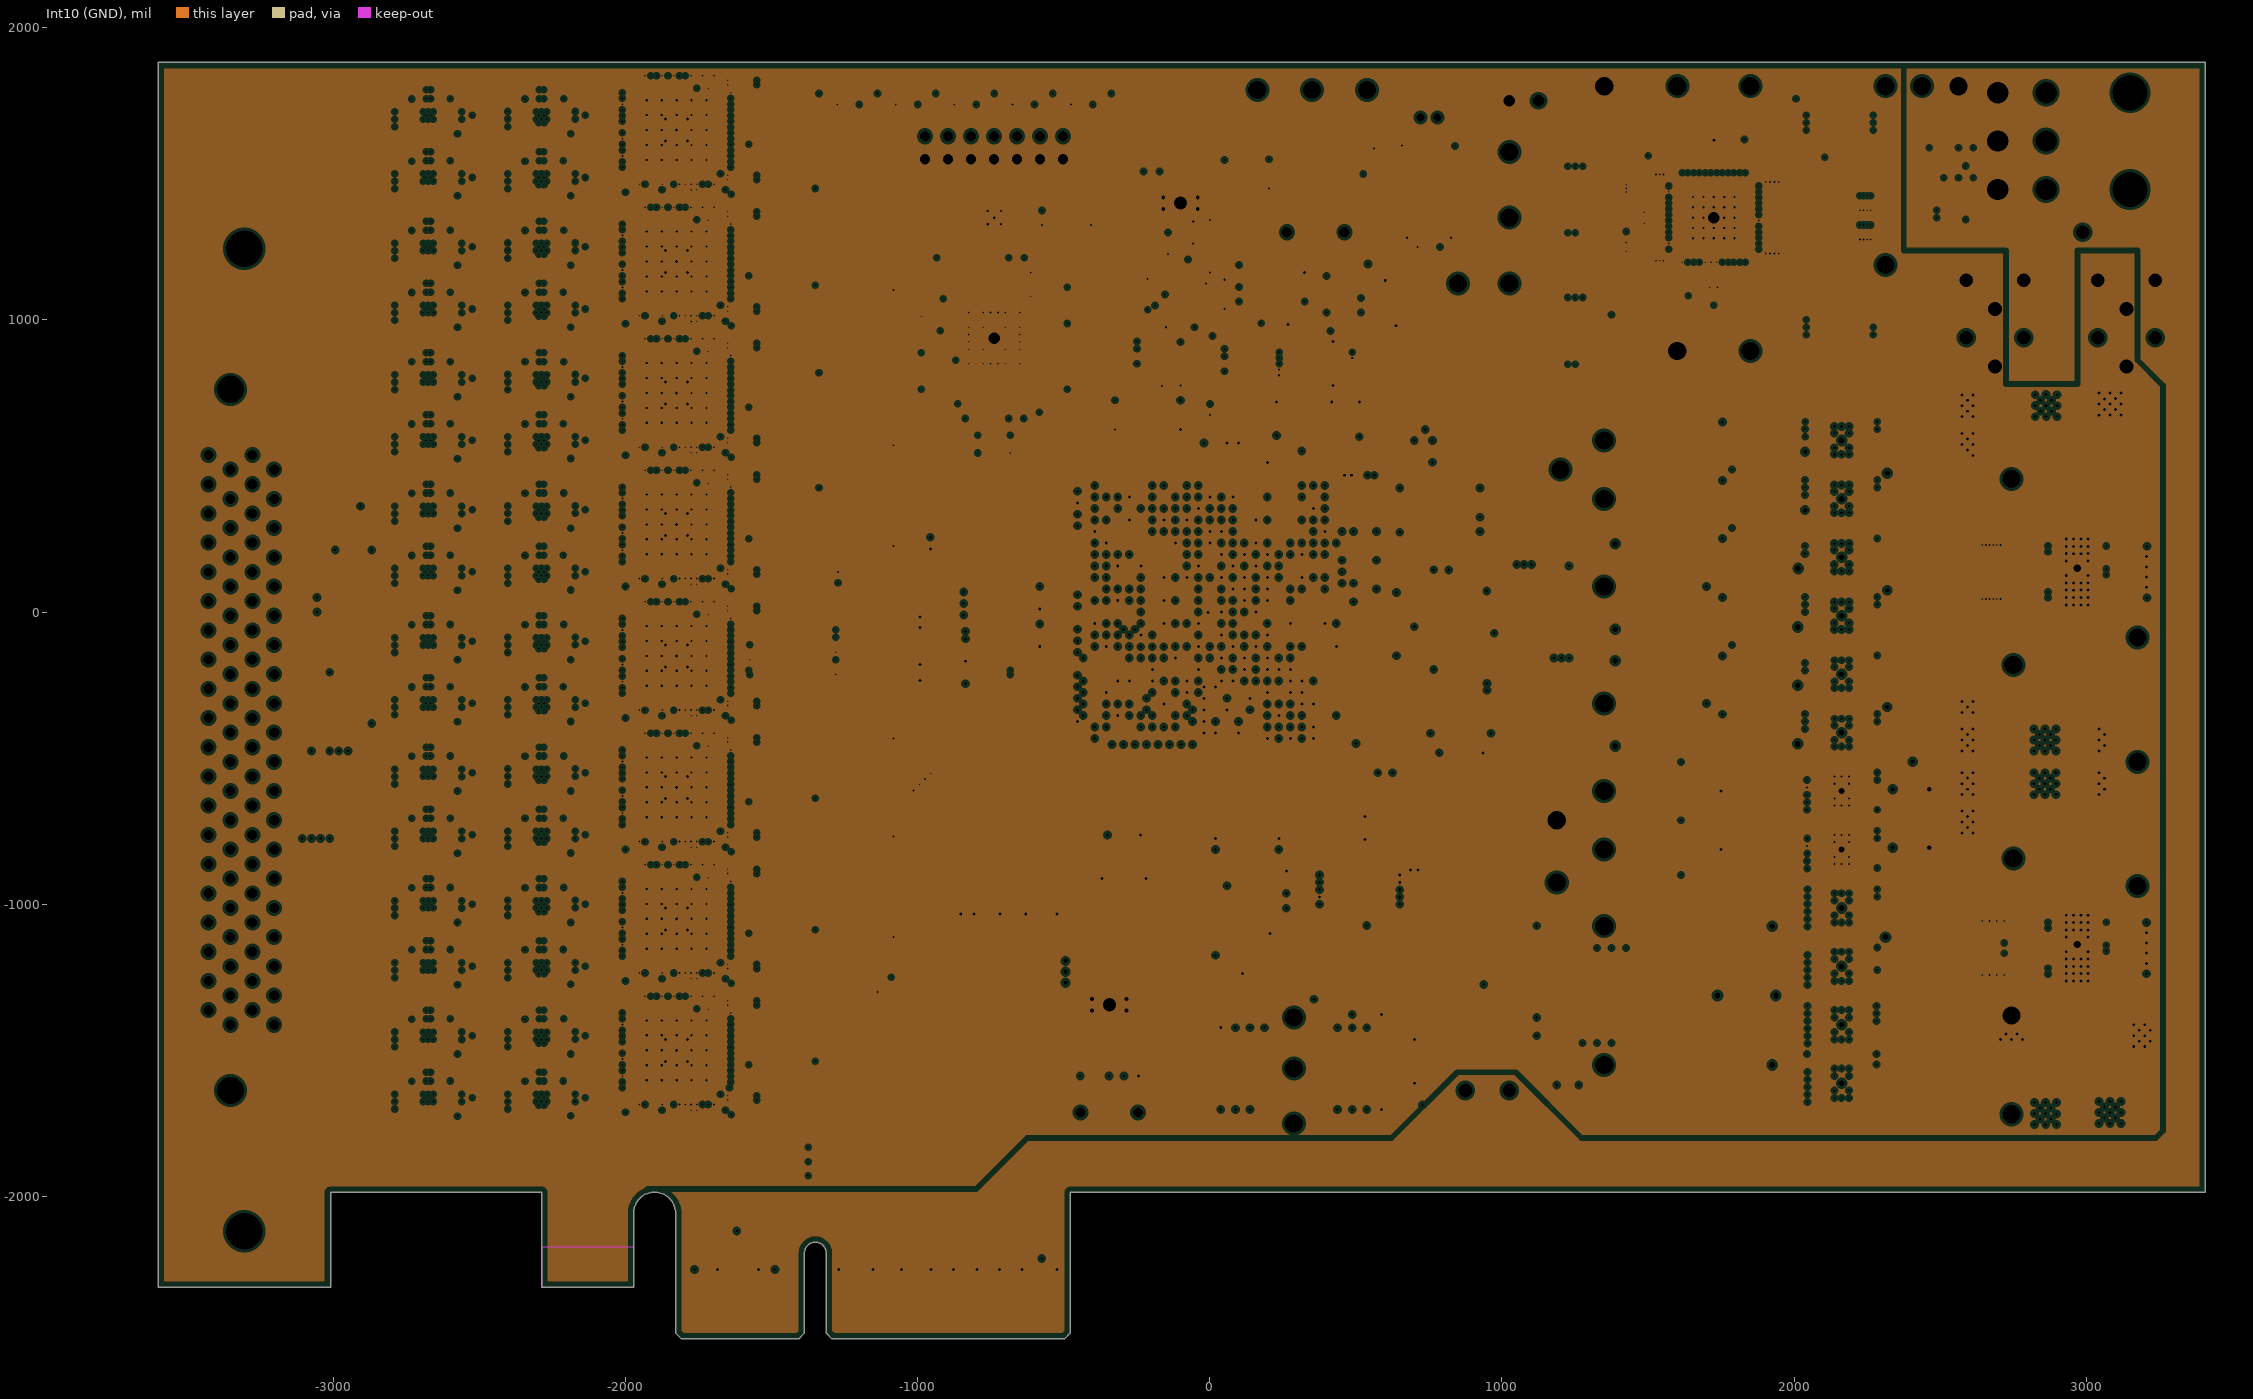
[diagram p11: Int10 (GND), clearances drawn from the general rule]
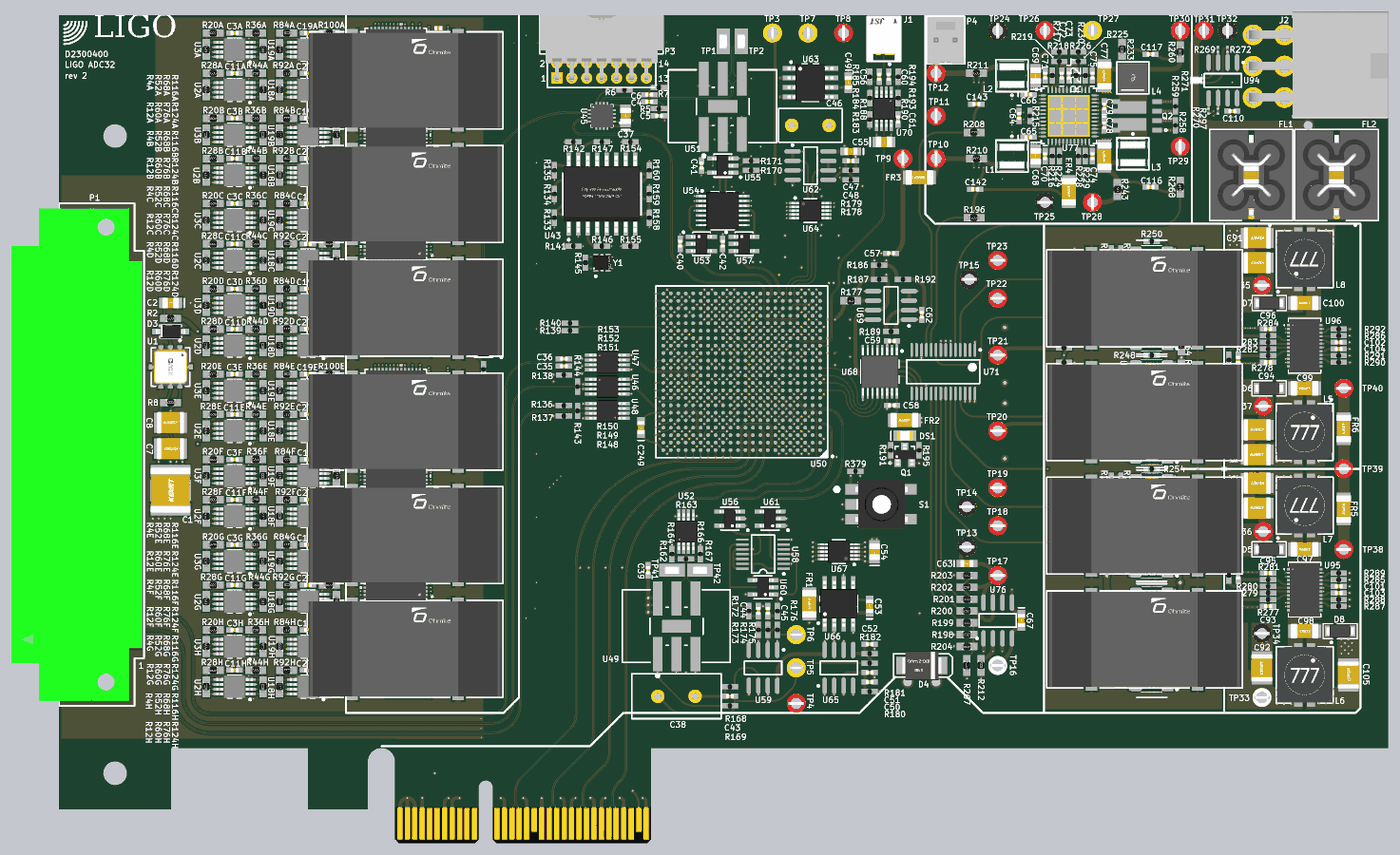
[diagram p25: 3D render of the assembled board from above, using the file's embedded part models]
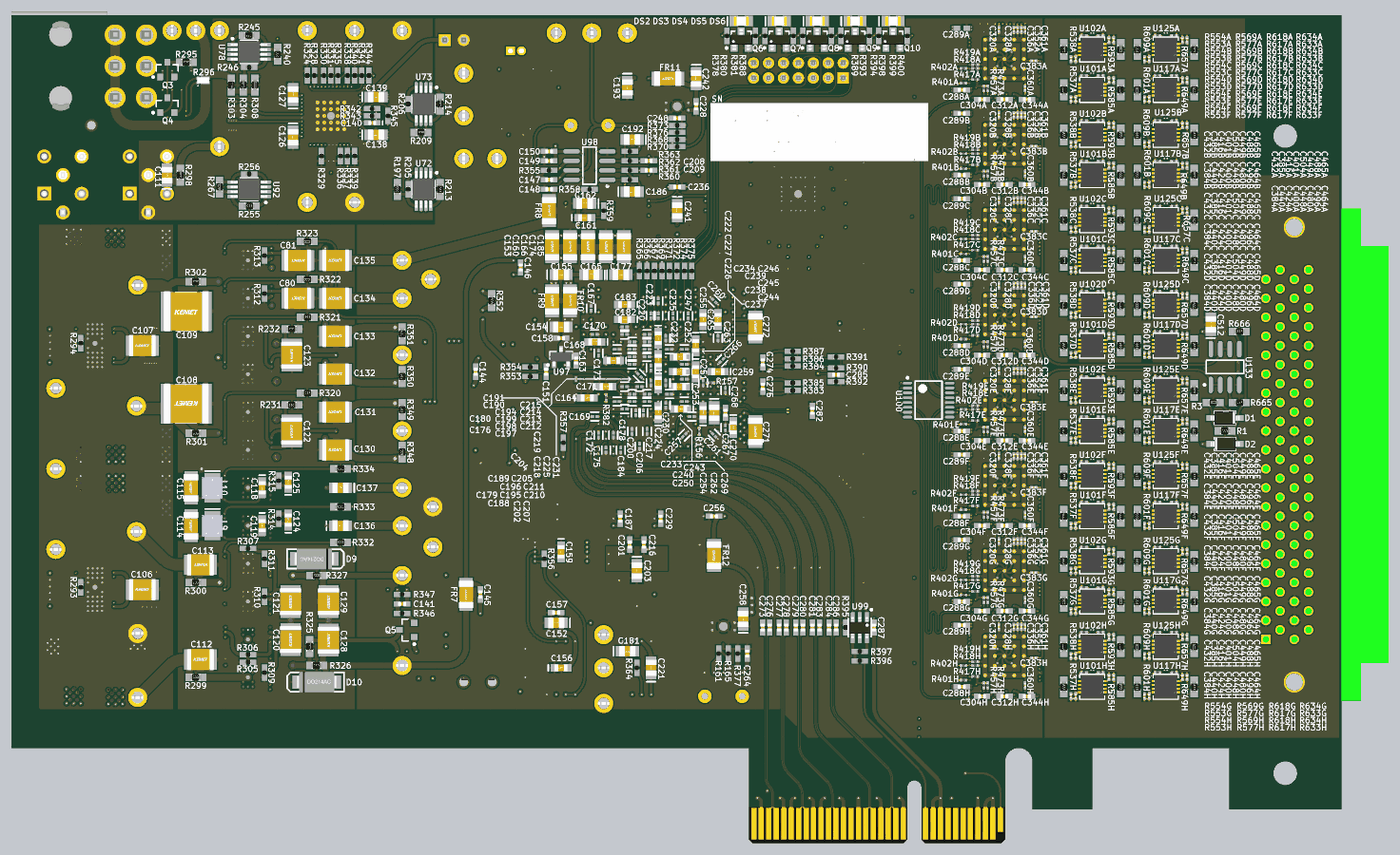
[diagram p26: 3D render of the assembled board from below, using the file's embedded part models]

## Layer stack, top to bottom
Top Solder: solder mask 1, SM-001, Dk 4
Top Layer: signal copper 1.378
Dielectric 1: prepreg 3.8, PP-013, Dk 4.3
Int1 (GND): plane copper 1.378, net (Multiple Nets)
Dielectric 2: core 4, Core-011, Dk 4.4
Int2 (AVDD): plane copper 1.378, net (Multiple Nets)
Dielectric 3: prepreg 3.8, PP-013, Dk 4.3
Int3 (DVDD): plane copper 1.378, net (Multiple Nets)
Dielectric 4: core 4, Core-011, Dk 4.4
Int4 (GND): plane copper 1.378, net (Multiple Nets)
Dielectric 5: prepreg 4.2, PP-014, Dk 4.2
Int5 (ST): signal copper 1.378
Dielectric 6: core 4, Core-011, Dk 4.4
Int6 (SB): signal copper 1.378
Dielectric 7: prepreg 4.2, PP-014, Dk 4.2
Int8 (AGND): plane copper 1.378, net (Multiple Nets)
Dielectric 8: core 4, Core-011, Dk 4.4
Int7 (AVCC): plane copper 1.378, net (Multiple Nets)
Dielectric 9: prepreg 3.8, PP-013, Dk 4.3
Int9 (VCCA): plane copper 1.378, net (Multiple Nets)
Dielectric 10: core 4, Core-011, Dk 4.4
Int10 (GND): plane copper 1.378, net (Multiple Nets)
Dielectric 11: prepreg 3.8, PP-013, Dk 4.3
Bottom Layer: signal copper 1.378
Bottom Solder: solder mask 1, SM-001, Dk 4

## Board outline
-3600,-2310.33 -3009.45,-2310.33 -3009.45,-1985.53 -2287.01,-1985.53 -2287.01,-2310.33 -1972.05,-2310.33 -1972.05,-2057.38 cw(c-1900.2,-2057.38) -1828.35,-2057.38 -1828.35,-2467.81 -1808.66,-2487.5 -1407.09,-2487.5 -1387.4,-2467.81 -1387.4,-2194.19 cw(c-1350,-2194.19) -1312.6,-2194.19 -1312.6,-2467.81 -1292.91,-2487.5 -497.5,-2487.5 -477.5,-2467.5 -477.5,-1985.53 3407.87,-1985.53 3407.87,1881.35 -3600,1881.35

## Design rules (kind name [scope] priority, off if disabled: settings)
Clearance [All] p1: gap=7 ignorepadtopadclearanceinfootprint=TRUE except(0: Arc-Text Track-Text SMDPad-Text THPad-Text Via-Text Fill-Text Poly-Text Region-Text Text-Text Text-Hole; 2.7: Arc-Arc Arc-Track Arc-SMDPad Arc-THPad Arc-Via Track-Track Track-SMDPad Track-THPad Track-Via SMDPad-SMDPad SMDPad-THPad SMDPad-Via THPad-THPad THPad-Via Via-Via; 3: Arc-Hole Track-Hole SMDPad-Hole THPad-Hole Via-Hole; 5: Fill-Hole Poly-Hole Region-Hole)
ComponentClearance ComponentClearance_1 [InComponent('PCI-E Bracket') vs InComponent('Designator26')] p1: gap=10 collisioncheckmode=3 verticalgap=10 showdistances=FALSE
ComponentClearance [All] p2: gap=10 collisioncheckmode=3 verticalgap=10 showdistances=FALSE
DiffPairsRouting DiffPairsRouting_REFCLK [InDifferentialPairClass('PCIE Clocks')] p1: maxlimit=5 minlimit=3 mostfreqgap=5 toplayer_mingap=5 toplayer_minwidth=4 toplayer_maxwidth=4 toplayer_prefwidth=4 midlayer1_minwidth=6 midlayer1_maxwidth=6 midlayer1_prefwidth=6 midlayer2_minwidth=6 midlayer2_maxwidth=6 midlayer2_prefwidth=6 bottomlayer_mingap=5 bottomlayer_minwidth=4 bottomlayer_maxwidth=4 bottomlayer_prefwidth=4 maxuncoupledlength=19.68
DiffPairsRouting [InDifferentialPairClass('PCIe')] p2: maxlimit=5 minlimit=3.4 mostfreqgap=5 toplayer_maxgap=3.4 toplayer_prefgap=3.4 toplayer_minwidth=4.8 toplayer_maxwidth=4.8 toplayer_prefwidth=4.8 midlayer1_mingap=5 midlayer1_minwidth=6 midlayer1_maxwidth=6 midlayer1_prefwidth=6 midlayer2_mingap=5 midlayer2_minwidth=6 midlayer2_maxwidth=6 midlayer2_prefwidth=6 bottomlayer_maxgap=3.4 bottomlayer_prefgap=3.4 bottomlayer_minwidth=4.8 bottomlayer_maxwidth=4.8 bottomlayer_prefwidth=4.8 maxuncoupledlength=19.68
DiffPairsRouting DiffPairsRouting_Default [InDifferentialPairClass('All Differential Pairs')] p3: maxlimit=5 minlimit=4.02 mostfreqgap=5 toplayer_maxgap=4.02 toplayer_prefgap=4.02 toplayer_minwidth=4.02 toplayer_maxwidth=4.02 toplayer_prefwidth=4.02 midlayer1_mingap=5 midlayer1_minwidth=6 midlayer1_maxwidth=6 midlayer1_prefwidth=6 midlayer2_mingap=5 midlayer2_minwidth=6 midlayer2_maxwidth=6 midlayer2_prefwidth=6 bottomlayer_maxgap=4.02 bottomlayer_prefgap=4.02 bottomlayer_minwidth=4.02 bottomlayer_maxwidth=4.02 bottomlayer_prefwidth=4.02 maxuncoupledlength=19.68
FabricationTestPointUsage TestPointUsage [All] p1: valid=0 allowmultiple=FALSE
FabricationTestpoint Testpoint [All] p1: side=3 testpointundercomponent=TRUE minsize=40 maxsize=100 preferedsize=60 minholesize=20 maxholesize=40 preferedholesize=32 testpointgrid=1 allowsidetop=TRUE allowsidebottom=TRUE usegrid=TRUE gridtolerance=0.01
Height "PCI Express, Page 84, \"Component Height Constraints\" for solder side" [OnBottomLayer] p1: minheight=0 maxheight=105.12 prefheight=105.12
Height "PCI Express, Page 84, \"Component Height Constraints\" for component side" [OnTopLayer] p2: minheight=0 maxheight=569.68 prefheight=569.68
PlaneClearance [All] p1: clearance=10
PlaneConnect [All] p1: pad.planeconnectstyle=Relief pad.reliefexpansion=20 pad.reliefentries=4 pad.reliefconductorwidth=20 pad.reliefairgap=7 via.planeconnectstyle=Direct via.reliefexpansion=20 via.reliefentries=4 via.reliefconductorwidth=10 via.reliefairgap=10
PolygonConnect [All] p1: connectstyle=Direct reliefconductorwidth=10 reliefentries=4 polygonreliefangle="90 Angle" airgapwidth=10
RoomDefinition FrontEnd7 [InComponentClass('FrontEnd7')] p1: confinementstyle=ConfineIn formatcopy=TRUE lockcomponents=FALSE outline -2093.75,-868.75 -2868.75,-868.75 -2868.75,-1306.25 -2093.75,-1306.25
RoomDefinition ADC1 [InComponentClass('ADC1')] p2: confinementstyle=ConfineIn formatcopy=TRUE lockcomponents=FALSE outline -2018.75,1400 -1375,1400 -1375,1850 -2018.75,1850
RoomDefinition FrontEnd1 [InComponentClass('FrontEnd1')] p3: confinementstyle=ConfineIn formatcopy=TRUE lockcomponents=FALSE outline -2093.75,1831.25 -2868.75,1831.25 -2868.75,1393.75 -2093.75,1393.75
RoomDefinition FrontEnd2 [InComponentClass('FrontEnd2')] p4: confinementstyle=ConfineIn formatcopy=TRUE lockcomponents=FALSE outline -2093.75,1381.25 -2868.75,1381.25 -2868.75,943.75 -2093.75,943.75
RoomDefinition FrontEnd3 [InComponentClass('FrontEnd3')] p5: confinementstyle=ConfineIn formatcopy=TRUE lockcomponents=FALSE outline -2093.75,931.25 -2868.75,931.25 -2868.75,493.75 -2093.75,493.75
RoomDefinition FrontEnd4 [InComponentClass('FrontEnd4')] p6: confinementstyle=ConfineIn formatcopy=TRUE lockcomponents=FALSE outline -2093.75,481.25 -2868.75,481.25 -2868.75,43.75 -2093.75,43.75
RoomDefinition FrontEnd5 [InComponentClass('FrontEnd5')] p7: confinementstyle=ConfineIn formatcopy=TRUE lockcomponents=FALSE outline -2093.75,31.25 -2868.75,31.25 -2868.75,-406.25 -2093.75,-406.25
RoomDefinition FrontEnd6 [InComponentClass('FrontEnd6')] p8: confinementstyle=ConfineIn formatcopy=TRUE lockcomponents=FALSE outline -2093.75,-418.75 -2868.75,-418.75 -2868.75,-856.25 -2093.75,-856.25
RoomDefinition FrontEnd8 [InComponentClass('FrontEnd8')] p9: confinementstyle=ConfineIn formatcopy=TRUE lockcomponents=FALSE outline -2093.75,-1318.75 -2868.75,-1318.75 -2868.75,-1756.25 -2093.75,-1756.25
RoomDefinition ADC3 [InComponentClass('ADC3')] p10: confinementstyle=ConfineIn formatcopy=TRUE lockcomponents=FALSE outline -1375,943.75 -2087.5,943.75 -2087.5,500 -1375,500
RoomDefinition FPGA [InComponentClass('FPGA')] p11: confinementstyle=ConfineIn formatcopy=TRUE lockcomponents=FALSE outline -456.25,-456.25 456.25,-456.25 456.25,456.25 -456.25,456.25
RoomDefinition ADC4 [InComponentClass('ADC4')] p12: confinementstyle=ConfineIn formatcopy=TRUE lockcomponents=FALSE outline -1375,500 -2087.5,500 -2087.5,50 -1375,50
RoomDefinition "VCO Phase" [InComponentClass('VCO Phase')] p13: confinementstyle=ConfineIn formatcopy=TRUE lockcomponents=FALSE outline 793.75,-681.25 -675.12,-681.25 -675.12,-1875 793.75,-1875
RoomDefinition "VCO Phase 2" [InComponentClass('VCO Phase 2')] p14: confinementstyle=ConfineIn formatcopy=TRUE lockcomponents=FALSE outline -400,568.75 650,568.75 650,1875 -400,1875
RoomDefinition ADC8 [InComponentClass('ADC8')] p15: confinementstyle=ConfineIn formatcopy=TRUE lockcomponents=FALSE outline -1375,-1300 -2087.5,-1300 -2087.5,-1750 -1375,-1750
RoomDefinition ADC7 [InComponentClass('ADC7')] p16: confinementstyle=ConfineIn formatcopy=TRUE lockcomponents=FALSE outline -1375,-850 -2087.5,-850 -2087.5,-1300 -1375,-1300
RoomDefinition ADC6 [InComponentClass('ADC6')] p17: confinementstyle=ConfineIn formatcopy=TRUE lockcomponents=FALSE outline -1375,-400 -2087.5,-400 -2087.5,-850 -1375,-850
RoomDefinition ADC5 [InComponentClass('ADC5')] p18: confinementstyle=ConfineIn formatcopy=TRUE lockcomponents=FALSE outline -1375,50 -2087.5,50 -2087.5,-400 -1375,-400
RoomDefinition ADC2 [InComponentClass('ADC2')] p19: confinementstyle=ConfineIn formatcopy=TRUE lockcomponents=FALSE outline -1375,1400 -2087.5,1400 -2087.5,943.75 -1375,943.75
RoutingCorners [All] p1: cornerstyle=Round minsetback=100 maxsetback=100
RoutingVias [All] p1: holewidth=10 width=20 viastyle="Through Hole" minholewidth=6 minwidth=12 maxholewidth=28 maxwidth=50
SilkToSolderMaskClearance SilkscreenOverComponentPads [IsPad] p1: minsilkscreentomaskgap=10 clearancetoexposedcopper=TRUE
SolderMaskExpansion [All] p1: expansion=0 istentingtop=FALSE
SupplyNets "Schematic Supply Nets_29" [InNet('P1_5V0')] p1: voltage=0.000
SupplyNets "Schematic Supply Nets_28" [InNet('VREF-PH')] p2: voltage=0.000
SupplyNets "Schematic Supply Nets_37" [InNet('GND')] p3: voltage=0.000
SupplyNets "Schematic Supply Nets_36" [InNet('DVDDR1V8')] p4: voltage=0.000
SupplyNets "Schematic Supply Nets_35" [InNet('VCC1V0')] p5: voltage=0.000
SupplyNets "Schematic Supply Nets_34" [InNet('AGND')] p6: voltage=0.000
SupplyNets "Schematic Supply Nets_33" [InNet('EXTGND')] p7: voltage=0.000
SupplyNets "Schematic Supply Nets_32" [InNet('P2_5V0')] p8: voltage=0.000
SupplyNets "Schematic Supply Nets_31" [InNet('BUS12V')] p9: voltage=0.000
SupplyNets "Schematic Supply Nets_30" [InNet('-15V')] p10: voltage=0.000
SupplyNets "Schematic Supply Nets_27" [InNet('VCC')] p11: voltage=0.000
SupplyNets "Schematic Supply Nets_26" [InNet('XADCVCC')] p12: voltage=0.000
SupplyNets "Schematic Supply Nets_25" [InNet('AVCC')] p13: voltage=0.000
SupplyNets "Schematic Supply Nets_24" [InNet('VCC2')] p14: voltage=0.000
SupplyNets "Schematic Supply Nets_23" [InNet('+15V')] p15: voltage=0.000
SupplyNets "Schematic Supply Nets_22" [InNet('VREG')] p16: voltage=0.000
SupplyNets "Schematic Supply Nets_21" [InNet('EXT12V')] p17: voltage=0.000
SupplyNets "Schematic Supply Nets_20" [InNet('DVDD1V8')] p18: voltage=0.000
SupplyNets "Schematic Supply Nets_19" [InNet('AVDDL1V8')] p19: voltage=0.000
SupplyNets "Schematic Supply Nets_18" [InNet('VCC2V5')] p20: voltage=0.000
SupplyNets "Schematic Supply Nets_17" [InNet('DVDDL1V8')] p21: voltage=0.000
SupplyNets "Schematic Supply Nets_16" [InNet('12VF')] p22: voltage=0.000
SupplyNets "Schematic Supply Nets_15" [InNet('DVDD5V0')] p23: voltage=0.000
SupplyNets "Schematic Supply Nets_14" [InNet('VCC1V8')] p24: voltage=0.000
SupplyNets "Schematic Supply Nets_13" [InNet('XADCGND')] p25: voltage=0.000
SupplyNets "Schematic Supply Nets_12" [InNet('SW+2V5')] p26: voltage=0.000
SupplyNets "Schematic Supply Nets_11" [InNet('AVDDR1V8')] p27: voltage=0.000
SupplyNets "Schematic Supply Nets_10" [InNet('AVTT')] p28: voltage=0.000
SupplyNets "Schematic Supply Nets_9" [InNet('SW+6V')] p29: voltage=0.000
SupplyNets "Schematic Supply Nets_8" [InNet('BUS3.3V')] p30: voltage=0.000
SupplyNets "Schematic Supply Nets_7" [InNet('VREF-PH2')] p31: voltage=0.000
SupplyNets "Schematic Supply Nets_6" [InNet('SENS_120f_N')] p32: voltage=0.000
SupplyNets "Schematic Supply Nets_5" [InNet('AVCC1V8')] p33: voltage=0.000
SupplyNets "Schematic Supply Nets_4" [InNet('AVDD1V8')] p34: voltage=0.000
SupplyNets "Schematic Supply Nets_3" [InNet('12V')] p35: voltage=0.000
SupplyNets "Schematic Supply Nets_2" [InNet('12VA')] p36: voltage=0.000
SupplyNets "Schematic Supply Nets_1" [InNet('AVDD5V0')] p37: voltage=0.000
SupplyNets "Schematic Supply Nets" [InNet('VREG2')] p38: voltage=0.000
UnRoutedNet [All] p1: checkbadconnections=TRUE
Width [All] p1: maxlimit=196.85 minlimit=3 preferedwidth=5 minimp=50.000000 maximp=50.000000 favimp=50.000000 checkconnectedcopper=TRUE
20 further rules are at their usual default settings.

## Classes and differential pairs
differential pair class PCIe: PCIE.PCIE_RX0 PCIE.PCIE_RX1 PCIE.PCIE_RX2 PCIE.PCIE_RX3 PER0 PER1 PER2 PER3
differential pair class "PCIe Clocks": ACLK.OSCCLKA AVCOCLK2 CLK_E CLK_O TRG
component class "VCO Phase": C38 C39 C43 C44 C45 C50 C51 C52 C53 C54 C152 C156 C157 C159 C181 C187 C201 C203 C216 C221 C229 C256 C258 C264 FR1 FR12 R161 R162 R163 R164 R165 R166 R167 R168 R169 R172 R173 R174 R175 R176 R180 R181 R182 R356 R364 R377 TP4 TP5 TP6 TP41 TP42 U49 U52 U56 U58 U59 U60 U61 U65 U66 U67
component class "Power Supplies": MP1 MP2 MP3 MP4 MP5 MP6 MP7 MP8 MP9 MP10
component class "VCO Phase 2": C4 C5 C6 C37 C40 C41 C42 C46 C47 C48 C49 C147 C148 C149 C150 C161 C162 C186 C192 C193 C208 C209 C228 C236 C241 C242 C248 FR8 FR11 R5 R6 R7 R170 R171 R178 R179 R355 R358 R359 R360 R361 R362 R363 R368 R370 R373 R376 TP1 TP2 TP3 TP7 TP8 U45 U51 U53 U54 U55 U57 U62 U63 U64 U98
component class FrontEnd8: C3H C11H C19H C27H C384H C385H C400H C401H C416H C424H C432H C440H C448H C449H C464H C465H C480H C488H C496H C504H R4H R12H R20H R28H R36H R44H R52H R60H R68H R76H R84H R92H R100H R108H R116H R124H R537H R538H R553H R554H R569H R577H R585H R593H R601H R609H R617H R618H R633H R634H R649H R657H U2H U3H U18H U19H U101H U102H U117H U125H
component class FrontEnd7: C3G C11G C19G C27G C384G C385G C400G C401G C416G C424G C432G C440G C448G C449G C464G C465G C480G C488G C496G C504G R4G R12G R20G R28G R36G R44G R52G R60G R68G R76G R84G R92G R100G R108G R116G R124G R537G R538G R553G R554G R569G R577G R585G R593G R601G R609G R617G R618G R633G R634G R649G R657G U2G U3G U18G U19G U101G U102G U117G U125G
component class FrontEnd6: C3F C11F C19F C27F C384F C385F C400F C401F C416F C424F C432F C440F C448F C449F C464F C465F C480F C488F C496F C504F R4F R12F R20F R28F R36F R44F R52F R60F R68F R76F R84F R92F R100F R108F R116F R124F R537F R538F R553F R554F R569F R577F R585F R593F R601F R609F R617F R618F R633F R634F R649F R657F U2F U3F U18F U19F U101F U102F U117F U125F
component class FrontEnd5: C3E C11E C19E C27E C384E C385E C400E C401E C416E C424E C432E C440E C448E C449E C464E C465E C480E C488E C496E C504E R4E R12E R20E R28E R36E R44E R52E R60E R68E R76E R84E R92E R100E R108E R116E R124E R537E R538E R553E R554E R569E R577E R585E R593E R601E R609E R617E R618E R633E R634E R649E R657E U2E U3E U18E U19E U101E U102E U117E U125E
component class ADC8: C288H C289H C304H C312H C320H C328H C336H C344H C352H C360H C361H C383H R401H R402H R417H R418H R419H R457H R473H U34H
component class ADC7: C288G C289G C304G C312G C320G C328G C336G C344G C352G C360G C361G C383G R401G R402G R417G R418G R419G R457G R473G U34G
component class ADC6: C288F C289F C304F C312F C320F C328F C336F C344F C352F C360F C361F C383F R401F R402F R417F R418F R419F R457F R473F U34F
component class ADC5: C288E C289E C304E C312E C320E C328E C336E C344E C352E C360E C361E C383E R401E R402E R417E R418E R419E R457E R473E U34E
component class FrontEnd4: C3D C11D C19D C27D C384D C385D C400D C401D C416D C424D C432D C440D C448D C449D C464D C465D C480D C488D C496D C504D R4D R12D R20D R28D R36D R44D R52D R60D R68D R76D R84D R92D R100D R108D R116D R124D R537D R538D R553D R554D R569D R577D R585D R593D R601D R609D R617D R618D R633D R634D R649D R657D U2D U3D U18D U19D U101D U102D U117D U125D
component class FrontEnd3: C3C C11C C19C C27C C384C C385C C400C C401C C416C C424C C432C C440C C448C C449C C464C C465C C480C C488C C496C C504C R4C R12C R20C R28C R36C R44C R52C R60C R68C R76C R84C R92C R100C R108C R116C R124C R537C R538C R553C R554C R569C R577C R585C R593C R601C R609C R617C R618C R633C R634C R649C R657C U2C U3C U18C U19C U101C U102C U117C U125C
component class ADC4: C288D C289D C304D C312D C320D C328D C336D C344D C352D C360D C361D C383D R401D R402D R417D R418D R419D R457D R473D U34D
component class ADC3: C288C C289C C304C C312C C320C C328C C336C C344C C352C C360C C361C C383C R401C R402C R417C R418C R419C R457C R473C U34C
channel class AdcDaughterFrontEnd: FrontEnd1 FrontEnd2 FrontEnd3 FrontEnd4 FrontEnd5 FrontEnd6 FrontEnd7 FrontEnd8
channel class AD32_Conv: ADC1 ADC2 ADC3 ADC4 ADC5 ADC6 ADC7 ADC8
component class FrontEnd2: C3B C11B C19B C27B C384B C385B C400B C401B C416B C424B C432B C440B C448B C449B C464B C465B C480B C488B C496B C504B R4B R12B R20B R28B R36B R44B R52B R60B R68B R76B R84B R92B R100B R108B R116B R124B R537B R538B R553B R554B R569B R577B R585B R593B R601B R609B R617B R618B R633B R634B R649B R657B U2B U3B U18B U19B U101B U102B U117B U125B
component class FrontEnd1: C3A C11A C19A C27A C384A C385A C400A C401A C416A C424A C432A C440A C448A C449A C464A C465A C480A C488A C496A C504A R4A R12A R20A R28A R36A R44A R52A R60A R68A R76A R84A R92A R100A R108A R116A R124A R537A R538A R553A R554A R569A R577A R585A R593A R601A R609A R617A R618A R633A R634A R649A R657A U2A U3A U18A U19A U101A U102A U117A U125A
component class ADC2: C288B C289B C304B C312B C320B C328B C336B C344B C352B C360B C361B C383B R401B R402B R417B R418B R419B R457B R473B U34B
component class ADC1: C288A C289A C304A C312A C320A C328A C336A C344A C352A C360A C361A C383A R401A R402A R417A R418A R419A R457A R473A U34A
net class PG[10..0]: PG0 PG1 PG2 PG3 PG4 PG5 PG6 PG7 PG8 PG9 PG10
component class PRG: C55 C56 C60 C61 C257 C261 DS1 J1 P3 Q1 R133 R134 R135 R139 R140 R141 R142 R145 R146 R147 R154 R155 R158 R159 R160 R183 R184 R185 R188 R190 R191 R193 R194 R195 R365 R366 R367 R369 R371 R372 R374 R375 R379 S1 U43 U44 U70 Y1
component class FPGA: C153 C160 C164 C166 C167 C168 C169 C170 C171 C173 C174 C176 C179 C180 C182 C183 C185 C189 C190 C191 C194 C195 C196 C197 C198 C199 C205 C210 C211 C212 C213 C214 C215 C218 C219 C220 C222 C223 C224 C225 C226 C227 C230 C231 C232 C233 C234 C235 C237 C238 C239 C240 C243 C244 C245 C246 C247 C249 C250 C251 C252 C253 C254 C255 C259 C260 C263 C265 C266 C267 C268 C270 C271 C272 DS2 DS3 DS4 DS5 DS6 Q6 Q7 Q8 Q9 Q10 R378 R380 R381 R388 R389 R393 R394 R398 R399 R400
component class "FPGA INTERFACE": R357 U50
net class JTAG[1..5]: JTAG1 JTAG2 JTAG3 JTAG4 JTAG5
component class Designator: C114 C115 C118 C119 C124 C125 C136 C137 C172 C175 C178 C184 C188 C200 C202 C206 C207 C217 C269 C273 C276 C277 C278 C279 C280 C281 C283 C284 C286 C287 D4 FL1 FL2 J2 L9 L10 R234 R235 R241 R242 R253 R254 R271 R296 R314 R315 R395 R396 R397 TP18 TP19 TP31 TP32 U83 U84 U99
component class ChassisTimingInterfacePCIE: P2
net class XMUX[3..0]: SQSPI.XMUX0 SQSPI.XMUX1 SQSPI.XMUX2 SQSPI.XMUX3
component class ADC: C57 C58 C59 C62 C63 C67 C110 C116 C117 C141 C142 C143 C144 C145 C146 C151 C154 C155 C158 C163 C204 FR2 FR3 FR4 FR7 FR9 FR10 Q3 Q4 Q5 R177 R186 R187 R189 R192 R196 R197 R198 R199 R200 R201 R202 R203 R204 R205 R206 R207 R208 R209 R212 R213 R214 R233 R240 R245 R246 R255 R256 R267 R268 R269 R270 R272 R295 R297 R303 R304 R308 R320 R321 R322 R323 R325 R332 R333 R334 R346 R347 R352 R353 R354 TP9 U68 U69 U71 U72 U73 U76 U78 U92 U94 U97 W3
component class ADC_TOP: C35 C36 C274 C275 C282 C285 LOGO1 P1 R136 R137 R138 R143 R144 R148 R149 R150 R151 R152 R153 R156 R157 R382 R383 R384 R385 R386 R387 R390 R391 R392 U46 U47 U48
component class "Pos Power": C84 C85 C88 C89 C90 C91 C94 C96 C99 C100 C102 C104 C107 C108 C109 D6 D7 FR6 L5 L8 R275 R276 R278 R282 R283 R284 R286 R290 R291 R292 R294 R301 R302 TP35 TP37 TP40 U96 W2
component class "Linear Supplies": C80 C81 C122 C123 C130 C131 C132 C133 C134 C135 R220 R221 R222 R223 R231 R232 R247 R248 R249 R250 R261 R262 R263 R264 R265 R266 R312 R313 R316 R317 R318 R319 R348 R349 R350 R351 TP15 TP20 TP21 TP22 TP23 U85 U86 U87 U88 U89 U90
component class PowerFPGA: C64 C65 C66 C68 C69 C70 C71 C72 C73 C74 C75 C76 C77 C78 C79 C111 C126 C127 C138 C139 C140 L1 L2 L3 L4 P4 Q2 R210 R211 R215 R216 R217 R218 R219 R224 R225 R226 R227 R228 R229 R230 R243 R258 R259 R260 R298 R324 R328 R329 R330 R331 R335 R336 R337 R338 R339 R340 R341 R342 R343 R344 R345 TP10 TP11 TP12 TP14 TP24 TP25 TP26 TP27 TP28 TP29 TP30 U77
component class "Diff Power": C82 C83 C86 C87 C92 C93 C95 C97 C98 C101 C103 C105 C106 C112 C113 C120 C121 C128 C129 D5 D8 D9 D10 FR5 L6 L7 R236 R237 R238 R239 R244 R251 R252 R257 R273 R274 R277 R279 R280 R281 R285 R287 R288 R289 R293 R299 R300 R305 R306 R307 R309 R310 R311 R326 R327 TP13 TP16 TP17 TP33 TP34 TP36 TP38 TP39 U79 U80 U81 U82 U95 W1
component class Analog: C1 C2 C7 C8 C165 C177 C262 C512 D1 D2 D3 R1 R2 R3 R8 R132 R665 R666 U1 U42 U100 U133
differential pair VCOCLK: +VCOCLK_P -VCOCLK_N
differential pair AVCOCLK2: +AVCOCLK2_P -AVCOCLK2_N
differential pair EXTCLK.CAUX: +EXTCLK.CAUX_P -EXTCLK.CAUX_N
differential pair CLK_AUX: +CLK_AUX_P -CLK_AUX_N
differential pair CAUX: +CAUX_P -CAUX_N
differential pair OUT4H: +OUT4H_P -OUT4H_N
differential pair OUT4G: +OUT4G_P -OUT4G_N
differential pair OUT4F: +OUT4F_P -OUT4F_N
differential pair OUT4E: +OUT4E_P -OUT4E_N
differential pair OUT4D: +OUT4D_P -OUT4D_N
differential pair OUT4C: +OUT4C_P -OUT4C_N
differential pair OUT4B: +OUT4B_P -OUT4B_N
differential pair OUT4A: +OUT4A_P -OUT4A_N
differential pair OUT3H: +OUT3H_P -OUT3H_N
differential pair OUT3G: +OUT3G_P -OUT3G_N
differential pair OUT3F: +OUT3F_P -OUT3F_N
differential pair OUT3E: +OUT3E_P -OUT3E_N
differential pair OUT3D: +OUT3D_P -OUT3D_N
differential pair OUT3C: +OUT3C_P -OUT3C_N
differential pair OUT3B: +OUT3B_P -OUT3B_N
differential pair OUT3A: +OUT3A_P -OUT3A_N
differential pair OUT2H: +OUT2H_P -OUT2H_N
differential pair OUT2G: +OUT2G_P -OUT2G_N
differential pair OUT2F: +OUT2F_P -OUT2F_N
differential pair OUT2E: +OUT2E_P -OUT2E_N
differential pair OUT2D: +OUT2D_P -OUT2D_N
differential pair OUT2C: +OUT2C_P -OUT2C_N
differential pair OUT2B: +OUT2B_P -OUT2B_N
differential pair OUT2A: +OUT2A_P -OUT2A_N
differential pair OUT1H: +OUT1H_P -OUT1H_N
differential pair OUT1G: +OUT1G_P -OUT1G_N
differential pair OUT1F: +OUT1F_P -OUT1F_N
differential pair OUT1E: +OUT1E_P -OUT1E_N
differential pair OUT1D: +OUT1D_P -OUT1D_N
differential pair OUT1C: +OUT1C_P -OUT1C_N
differential pair OUT1B: +OUT1B_P -OUT1B_N
differential pair OUT1A: +OUT1A_P -OUT1A_N
differential pair ACLK.CNTROUTF: +ACLK.CNTROUTF_P -ACLK.CNTROUTF_N
differential pair CLOCK.CNTROUT: +CLOCK.CNTROUT_P -CLOCK.CNTROUT_N
differential pair ACLK.OSCCLKA: +ACLK.OSCCLKA_P -ACLK.OSCCLKA_N
differential pair ACLK.SYNCF: +ACLK.SYNCF_P -ACLK.SYNCF_N
differential pair CLKM_O: +CLKM_O_P -CLKM_O_N
differential pair ACLK.OSCCLKF: +ACLK.OSCCLKF_P -ACLK.OSCCLKF_N
differential pair AVCOCLK: +AVCOCLK_P -AVCOCLK_N
differential pair EXT.TRIGout: +EXT.TRIGout_P -EXT.TRIGout_N
differential pair TRG: +TRG_P -TRG_N
differential pair CLKO: +CLKO_P -CLKO_N
differential pair CLKE: +CLKE_P -CLKE_N
differential pair CLK_O: +CLK_O_P -CLK_O_N
differential pair CLK_E: +CLK_E_P -CLK_E_N
differential pair XADC: +XADC_P -XADC_N
differential pair XADC_REF: +XADC_REF_P -XADC_REF_N
differential pair PCIE.PCIE_TX3: +PCIE.PCIE_TX3_P -PCIE.PCIE_TX3_N
differential pair PCIE.PCIE_TX2: +PCIE.PCIE_TX2_P -PCIE.PCIE_TX2_N
differential pair PCIE.PCIE_TX1: +PCIE.PCIE_TX1_P -PCIE.PCIE_TX1_N
differential pair PCIE.PCIE_RX3: +PCIE.PCIE_RX3_P -PCIE.PCIE_RX3_N
differential pair PCIE.PCIE_RX2: +PCIE.PCIE_RX2_P -PCIE.PCIE_RX2_N
differential pair PCIE.PCIE_RX1: +PCIE.PCIE_RX1_P -PCIE.PCIE_RX1_N
differential pair PCIE.PCIE_TX0: +PCIE.PCIE_TX0_P -PCIE.PCIE_TX0_N
differential pair PCIE.PCIE_CLK: +PCIE.PCIE_CLK_P -PCIE.PCIE_CLK_N
differential pair PER3: +PER3_P -PER3_N
differential pair PER2: +PER2_P -PER2_N
differential pair PER1: +PER1_P -PER1_N
differential pair CLOCK.SYNC: +CLOCK.SYNC_P -CLOCK.SYNC_N
differential pair CLOCK.OSCCLK: +CLOCK.OSCCLK_P -CLOCK.OSCCLK_N
differential pair ANALOG4.A8: +ANALOG4.A8_P -ANALOG4.A8_N
differential pair ANALOG4.A7: +ANALOG4.A7_P -ANALOG4.A7_N
differential pair ANALOG4.A6: +ANALOG4.A6_P -ANALOG4.A6_N
differential pair ANALOG4.A5: +ANALOG4.A5_P -ANALOG4.A5_N
differential pair ANALOG4.A4: +ANALOG4.A4_P -ANALOG4.A4_N
differential pair ANALOG4.A3: +ANALOG4.A3_P -ANALOG4.A3_N
differential pair ANALOG4.A2: +ANALOG4.A2_P -ANALOG4.A2_N
differential pair ANALOG4.A1: +ANALOG4.A1_P -ANALOG4.A1_N
differential pair ANALOG3.A8: +ANALOG3.A8_P -ANALOG3.A8_N
differential pair ANALOG3.A7: +ANALOG3.A7_P -ANALOG3.A7_N
differential pair ANALOG3.A6: +ANALOG3.A6_P -ANALOG3.A6_N
differential pair ANALOG3.A5: +ANALOG3.A5_P -ANALOG3.A5_N
differential pair ANALOG3.A4: +ANALOG3.A4_P -ANALOG3.A4_N
differential pair ANALOG3.A3: +ANALOG3.A3_P -ANALOG3.A3_N
differential pair ANALOG3.A2: +ANALOG3.A2_P -ANALOG3.A2_N
differential pair ANALOG3.A1: +ANALOG3.A1_P -ANALOG3.A1_N
differential pair ANALOG2.A8: +ANALOG2.A8_P -ANALOG2.A8_N
differential pair ANALOG2.A7: +ANALOG2.A7_P -ANALOG2.A7_N
differential pair ANALOG2.A6: +ANALOG2.A6_P -ANALOG2.A6_N
differential pair ANALOG2.A5: +ANALOG2.A5_P -ANALOG2.A5_N
differential pair ANALOG2.A4: +ANALOG2.A4_P -ANALOG2.A4_N
differential pair ANALOG2.A3: +ANALOG2.A3_P -ANALOG2.A3_N
differential pair ANALOG2.A2: +ANALOG2.A2_P -ANALOG2.A2_N
differential pair ANALOG2.A1: +ANALOG2.A1_P -ANALOG2.A1_N
differential pair ANALOG1.A8: +ANALOG1.A8_P -ANALOG1.A8_N
differential pair ANALOG1.A7: +ANALOG1.A7_P -ANALOG1.A7_N
differential pair ANALOG1.A6: +ANALOG1.A6_P -ANALOG1.A6_N
differential pair ANALOG1.A5: +ANALOG1.A5_P -ANALOG1.A5_N
differential pair ANALOG1.A4: +ANALOG1.A4_P -ANALOG1.A4_N
differential pair ANALOG1.A3: +ANALOG1.A3_P -ANALOG1.A3_N
differential pair ANALOG1.A2: +ANALOG1.A2_P -ANALOG1.A2_N
differential pair ANALOG1.A1: +ANALOG1.A1_P -ANALOG1.A1_N
differential pair REFCLK: +REFCLK_P -REFCLK_N
differential pair PER0: +PER0_P -PER0_N
differential pair PCIE.PCIE_RX0: +PCIE.PCIE_RX0_P -PCIE.PCIE_RX0_N

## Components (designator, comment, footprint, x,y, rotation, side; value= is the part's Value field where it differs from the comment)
C1 "22uF" CC5650-2220 -3012.5,-625 r90 top
C2 "100n" CC2013-0805 -3012.5,362.5 r180 top
C3A "3.3n" CC1005-0402 -2675,1787.5 r0 top (schematic designator C3)
C3B "3.3n" CC1005-0402 -2675,1337.5 r0 top (schematic designator C3)
C3C "3.3n" CC1005-0402 -2675,887.5 r0 top (schematic designator C3)
C3D "3.3n" CC1005-0402 -2675,437.5 r0 top (schematic designator C3)
C3E "3.3n" CC1005-0402 -2675,-12.5 r0 top (schematic designator C3)
C3F "3.3n" CC1005-0402 -2675,-462.5 r0 top (schematic designator C3)
C3G "3.3n" CC1005-0402 -2675,-912.5 r0 top (schematic designator C3)
C3H "3.3n" CC1005-0402 -2675,-1362.5 r0 top (schematic designator C3)
C4 "10n" CC1005-0402 -487.5,1425 r0 top
C5 "NL" CC1005-0402 -436.25,1350 r0 top
C6 "10n" CC1005-0402 -487.5,1462.5 r0 top
C7 "10u" CC3225-1210 -3012.5,-406.25 r180 top
C8 "10u" CC3225-1210 -3012.5,-268.75 r0 top
C11A "3.3n" CC1005-0402 -2675,1575 r0 top (schematic designator C11)
C11B "3.3n" CC1005-0402 -2675,1125 r0 top (schematic designator C11)
C11C "3.3n" CC1005-0402 -2675,675 r0 top (schematic designator C11)
C11D "3.3n" CC1005-0402 -2675,225 r0 top (schematic designator C11)
C11E "3.3n" CC1005-0402 -2675,-225 r0 top (schematic designator C11)
C11F "3.3n" CC1005-0402 -2675,-675 r0 top (schematic designator C11)
C11G "3.3n" CC1005-0402 -2675,-1125 r0 top (schematic designator C11)
C11H "3.3n" CC1005-0402 -2675,-1575 r0 top (schematic designator C11)
C19A "3.3n" CC1005-0402 -2287.5,1787.5 r0 top (schematic designator C19)
C19B "3.3n" CC1005-0402 -2287.5,1337.5 r0 top (schematic designator C19)
C19C "3.3n" CC1005-0402 -2287.5,887.5 r0 top (schematic designator C19)
C19D "3.3n" CC1005-0402 -2287.5,437.5 r0 top (schematic designator C19)
C19E "3.3n" CC1005-0402 -2287.5,-12.5 r0 top (schematic designator C19)
C19F "3.3n" CC1005-0402 -2287.5,-462.5 r0 top (schematic designator C19)
C19G "3.3n" CC1005-0402 -2287.5,-912.5 r0 top (schematic designator C19)
C19H "3.3n" CC1005-0402 -2287.5,-1362.5 r0 top (schematic designator C19)
C27A "3.3n" CC1005-0402 -2287.5,1575 r0 top (schematic designator C27)
C27B "3.3n" CC1005-0402 -2287.5,1125 r0 top (schematic designator C27)
C27C "3.3n" CC1005-0402 -2287.5,675 r0 top (schematic designator C27)
C27D "3.3n" CC1005-0402 -2287.5,225 r0 top (schematic designator C27)
C27E "3.3n" CC1005-0402 -2287.5,-225 r0 top (schematic designator C27)
C27F "3.3n" CC1005-0402 -2287.5,-675 r0 top (schematic designator C27)
C27G "3.3n" CC1005-0402 -2287.5,-1125 r0 top (schematic designator C27)
C27H "3.3n" CC1005-0402 -2287.5,-1575 r0 top (schematic designator C27)
C35 "100n" CC1005-0402 -937.5,29.53 r0 top
C36 "100n" CC1005-0402 -937.5,68.9 r0 top
C37 "100n" CC2013-0805 -612.5,1350 r90 top
C38 "470n" ECQPZ120060-5.0 -245.65,-1712.5 r180 top
C39 "100n" CC1005-0402 -493.75,-1047.5 r270 top
C40 "100n" CC1005-0402 -325,675 r90 top
C41 "100n" CC1005-0402 -212.5,1087.5 r270 top
C42 "100n" CC1005-0402 -100,675 r90 top
C43 "1.0n" CC1005-0402 -62.5,-1712.5 r180 top
C44 "1.0n" CC1005-0402 87.5,-1262.5 r270 top
C45 "1.0n" CC1005-0402 137.5,-1262.5 r90 top
C46 "470n" ECQPZ085045-5.0 460.63,1300 r180 top
C47 "1.0u" CC1608-0603 575,1162.5 r180 top
C48 "100n" CC1005-0402 575,1112.5 r180 top
C49 "1.0u" CC1608-0603 562.5,1525 r270 top
C50 "100n" CC1005-0402 675,-1637.5 r180 top
C51 "100n" CC1005-0402 675,-1587.5 r180 top
C52 "100n" CC1005-0402 675,-1437.5 r180 top
C53 "1.0u" CC1608-0603 675,-1237.5 r90 top
C54 "10u" CC2013-0805 700,-950 r90 top
C55 "100n" CC2013-0805 750,1212.5 r0 top
C56 "100n" CC1005-0402 725,1556.25 r270 top
C57 "1.0u" CC1005-0402 787.5,625 r180 top
C58 "100n" CC1005-0402 792.32,-177.17 r0 top
C59 "100n" CC1005-0402 792.32,162.5 r0 top
C60 "100n" CC1005-0402 775,1556.25 r270 top
C61 "10n" CC1005-0402 825,1331.25 r90 top
C62 "100p" CC1005-0402 950,300 r90 top
C63 "1.0u" CC1608-0603 1187.5,-1012.5 r0 top
C64 "1.0u" CC1005-0402 1462.5,1350 r270 top
C65 "100n" CC1005-0402 1512.5,1237.5 r0 top
C66 "100n" CC1005-0402 1512.5,1462.5 r0 top
C67 "1.0u" CC1608-0603 1475,-1312.5 r270 top
C68 "10u" CC2013-0805 1550,1137.5 r270 top
C69 "10u" CC2013-0805 1550,1562.5 r90 top
C70 "1.8n" CC1005-0402 1600,1137.5 r270 top
C71 "1.8n" CC1005-0402 1600,1562.5 r90 top
C72 "1.0u" CC1005-0402 1687.5,1562.5 r90 top
C73 "1.0u" CC1005-0402 1725,1562.5 r270 top
C74 "5.6n" CC1005-0402 1850,1137.5 r270 top
C75 "2.7n" CC1005-0402 1850,1562.5 r90 top
C76 "47u" CC3216-1206 1912.5,1137.5 r90 top
C77 "47u" CC3216-1206 1912.5,1562.5 r90 top
C78 "100n" CC1005-0402 1912.5,1300 r270 top
C79 "100n" CC1005-0402 1912.5,1400 r90 top
C80 "3.3uF" CC3225-1210 1900,387.5 r0 bottom
C81 "3.3uF" CC3225-1210 1900,587.5 r0 bottom
C82 "47n" CC1005-0402 2618.75,-1225 r270 top
C83 "47n" CC1005-0402 2618.75,-1075 r270 top
C84 "47n" CC1005-0402 2618.75,62.5 r270 top
C85 "47n" CC1005-0402 2618.75,212.5 r270 top
C86 "10u" CC3225-1210 2718.75,-718.75 r0 top
C87 "10u" CC3225-1210 2718.75,-587.5 r180 top
C88 "10u" CC3225-1210 2718.75,-437.5 r0 top
C89 "10u" CC3225-1210 2718.75,-306.25 r0 top
C90 "10u" CC3225-1210 2718.75,575 r180 top
C91 "10u" CC3225-1210 2718.75,706.25 r180 top
C92 "10u" CC3225-1210 2743.75,-1562.5 r90 top
C93 "100p" CC1005-0402 2776.25,-1237.5 r180 top
C94 "100p" CC1005-0402 2776.25,50 r180 top
C95 "100p" CC1005-0402 2776.25,-1062.5 r0 top
C96 "100p" CC1005-0402 2776.25,225 r0 top
C97 "2.2u" CC3216-1206 2968.75,-937.5 r0 top
C98 "2.2u" CC3216-1206 2968.75,-1368.75 r180 top
C99 "2.2u" CC3216-1206 2968.75,-87.5 r0 top
C100 "2.2u" CC3216-1206 2968.75,362.5 r0 top
C101 "100n" CC1005-0402 3148.75,-1132.5 r180 top
C102 "100n" CC1005-0402 3148.75,155 r180 top
C103 "100n" CC1005-0402 3148.75,-1167.5 r0 top
C104 "100n" CC1005-0402 3148.75,120 r0 top
C105 "10u" CC3225-1210 3200,-1600 r270 top
C106 "10u" CC3225-1210 2718.75,-1150 r180 bottom
C107 "10u" CC3225-1210 2718.75,137.5 r180 bottom
C108 "47u" CC5650-2220 2487.5,-168.75 r0 bottom
C109 "47u" CC5650-2220 2487.5,318.75 r180 bottom
C110 "100n" CC1005-0402 2587.5,1375 r180 top
C111 "10u" CC2013-0805 2589.07,1037.5 r90 bottom
C112 "10u" CC3225-1210 2412.5,-1518.75 r180 bottom
C113 "10u" CC3225-1210 2412.5,-1018.75 r0 bottom
C114 "47u" CC3216-1206 2462.5,-812.5 r270 bottom
C115 "47u" CC3216-1206 2462.5,-612.5 r270 bottom
C116 "100n" CC1005-0402 2156.25,975 r180 top
C117 "100n" CC1005-0402 2156.25,1675 r0 top
C118 "1.0u" CC1608-0603 2087.5,-612.5 r270 bottom
C119 "1.0u" CC1608-0603 2087.5,-812.5 r270 bottom
C120 "3.3uF" CC3225-1210 1937.5,-1412.5 r90 bottom
C121 "3.3uF" CC3225-1210 1937.5,-1212.5 r90 bottom
C122 "3.3uF" CC3225-1210 1931.25,-312.5 r90 bottom
C123 "3.3uF" CC3225-1210 1931.25,87.5 r90 bottom
C124 "4.7u" CC1608-0603 1950,-782.87 r90 bottom
C125 "4.7u" CC1608-0603 1950,-582.87 r90 bottom
C126 "10u" CC2013-0805 1925,1237.5 r270 bottom
C127 "10u" CC2013-0805 1925,1462.5 r90 bottom
C128 "10u" CC3225-1210 1737.5,-1416.54 r90 bottom
C129 "10u" CC3225-1210 1737.5,-1212.5 r90 bottom
C130 "10u" CC3225-1210 1700,-412.5 r180 bottom
C131 "10u" CC3225-1210 1700,-212.5 r180 bottom
C132 "10u" CC3225-1210 1700,-12.5 r180 bottom
C133 "10u" CC3225-1210 1700,187.5 r180 bottom
C134 "10u" CC3225-1210 1700,387.5 r180 bottom
C135 "10u" CC3225-1210 1700,587.5 r180 bottom
C136 "10u" CC2013-0805 1675,-812.5 r180 bottom
C137 "10u" CC2013-0805 1675,-612.5 r0 bottom
C138 "10u" CC2013-0805 1487.5,1250 r180 bottom
C139 "10u" CC2013-0805 1487.5,1450 r180 bottom
C140 "1.0u" CC1005-0402 1507.5,1312.5 r0 bottom
C141 "100n" CC1005-0402 1350,-1225 r0 bottom
C142 "100n" CC1005-0402 1231.25,962.5 r180 top
C143 "100n" CC1005-0402 1237.5,1412.5 r180 top
C144 "100n" CC1005-0402 962.5,0 r90 bottom
C145 "1.0u" CC1005-0402 937.5,-1175 r90 bottom
C146 "100p" CC1005-0402 725,550 r90 bottom
C147 "1.0n" CC1005-0402 575,1012.5 r0 bottom
C148 "100n" CC1005-0402 575,962.5 r180 bottom
C149 "100n" CC1005-0402 575,1112.5 r180 bottom
C150 "100n" CC1005-0402 575,1162.5 r180 bottom
C151 "NL" CC1005-0402 590.55,0 r90 bottom
C152 "10u" CC2013-0805 537.5,-1325 r0 bottom
C153 "47u" CC3216-1206 559.06,659.45 r270 bottom
C154 "10u" CC2013-0805 511.81,236.22 r180 bottom
C155 "10u" CC2013-0805 511.81,511.81 r180 bottom
C156 "1.0u" CC1608-0603 512.6,-1562.5 r180 bottom
C157 "100n" CC1005-0402 538.19,-1270.69 r180 bottom
C158 "100n" CC1005-0402 511.81,177.17 r180 bottom
C159 "1.0u" CC1608-0603 512.5,-950 r270 bottom
C160 "47u" CC3216-1206 464.57,659.45 r270 bottom
C161 "1.0u" CC1608-0603 387.5,812.5 r180 bottom
C162 "10u" CC2013-0805 387.5,887.5 r0 bottom
C163 "100n" CC1005-0402 433.07,59.06 r90 bottom
C164 "4.7u" CC1608-0603 374.02,-137.8 r180 bottom
C165 "100n" CC2013-0805 354.33,511.81 r0 bottom
C166 "47u" CC3216-1206 370.08,659.45 r270 bottom
C167 "470n" FP-CL03-IPC_B 354.33,334.65 r270 bottom
C168 "4.7u" CC1608-0603 334.65,157.48 r0 bottom
C169 "470n" FP-CL03-IPC_B 334.65,-236.22 r0 bottom
C170 "470n" FP-CL03-IPC_B 334.65,196.85 r0 bottom
C171 "4.7u" CC1608-0603 275.59,-78.74 r180 bottom
C172 "470n" FP-CL03-IPC_B 314.96,-334.65 r90 bottom
C173 "470n" FP-CL03-IPC_B 314.96,98.43 r270 bottom
C174 "47u" CC3216-1206 275.59,659.45 r270 bottom
C175 "470n" FP-CL03-IPC_B 275.59,-413.39 r90 bottom
C176 "4.7u" CC1608-0603 236.22,59.06 r0 bottom
C177 "100n" CC2013-0805 196.85,511.81 r180 bottom
C178 "470n" FP-CL03-IPC_B 236.22,-334.65 r270 bottom
C179 "470n" FP-CL03-IPC_B 216.54,-157.48 r0 bottom
C180 "470n" FP-CL03-IPC_B 216.54,118.11 r0 bottom
C181 "NL" CC2013-0805 162.5,-1475 r180 bottom
C182 "4.7u" CC1608-0603 177.17,275.59 r0 bottom
C183 "4.7u" CC1608-0603 177.17,354.33 r0 bottom
C184 "470n" FP-CL03-IPC_B 196.85,-413.39 r270 bottom
C185 "47u" CC3216-1206 181.1,659.45 r270 bottom
C186 "NL" CC2013-0805 137.5,950 r180 bottom
C187 "100n" CC1005-0402 200,-775 r270 bottom
C188 "470n" FP-CL03-IPC_B 177.17,-196.85 r0 bottom
C189 "470n" FP-CL03-IPC_B 177.17,-78.74 r0 bottom
C190 "470n" FP-CL03-IPC_B 177.17,196.85 r180 bottom
C191 "470n" FP-CL03-IPC_B 177.17,236.22 r0 bottom
C192 "NL" CC2013-0805 137.5,1225 r0 bottom
C193 "10u" CC2013-0805 162.5,1500 r270 bottom
C194 "470n" FP-CL03-IPC_B 137.8,157.48 r0 bottom
C195 "470n" FP-CL03-IPC_B 137.8,-157.48 r180 bottom
C196 "470n" FP-CL03-IPC_B 137.8,-118.11 r0 bottom
C197 "470n" FP-CL03-IPC_B 137.8,39.37 r180 bottom
C198 "470n" FP-CL03-IPC_B 137.8,78.74 r180 bottom
C199 "470n" FP-CL03-IPC_B 137.8,118.11 r180 bottom
C200 "470n" FP-CL03-IPC_B 137.8,-314.96 r270 bottom
C201 "100n" CC1005-0402 150,-912.5 r270 bottom
C202 "470n" FP-CL03-IPC_B 118.11,-216.54 r90 bottom
C203 "10u" CC2013-0805 112.5,-1050 r270 bottom
C204 "NL" FP-CL03-IPC_B 98.43,-19.68 r225 bottom
C205 "470n" FP-CL03-IPC_B 98.43,-78.74 r180 bottom
C206 "470n" FP-CL03-IPC_B 98.43,-393.7 r90 bottom
C207 "470n" FP-CL03-IPC_B 78.74,-216.54 r90 bottom
C208 "1.0n" CC1005-0402 50,1112.5 r0 bottom
C209 "1.0n" CC1005-0402 50,1062.5 r180 bottom
C210 "470n" FP-CL03-IPC_B 59.06,-157.48 r180 bottom
C211 "470n" FP-CL03-IPC_B 59.06,-118.11 r0 bottom
C212 "470n" FP-CL03-IPC_B 59.06,78.74 r180 bottom
C213 "470n" FP-CL03-IPC_B 59.06,118.11 r0 bottom
C214 "470n" FP-CL03-IPC_B 59.06,157.48 r0 bottom
C215 "470n" FP-CL03-IPC_B 59.06,196.85 r180 bottom
C216 "100n" CC1005-0402 75,-912.5 r270 bottom
C217 "470n" FP-CL03-IPC_B 59.06,-314.96 r90 bottom
C218 "470n" FP-CL03-IPC_B 39.37,-59.05 r270 bottom
C219 "470n" FP-CL03-IPC_B 39.37,19.69 r270 bottom
C220 "470n" FP-CL03-IPC_B 39.37,295.28 r90 bottom
C221 "NL" CC2013-0805 37.5,-1562.5 r90 bottom
C222 "470n" FP-CL03-IPC_B 0,295.28 r90 bottom
C223 "470n" FP-CL03-IPC_B 0,374.02 r270 bottom
C224 "4.7u" CC1608-0603 0,-216.54 r90 bottom
C225 "4.7u" CC1608-0603 0,-59.06 r270 bottom
C226 "4.7u" CC1608-0603 0,59.06 r90 bottom
C227 "4.7u" CC1608-0603 0,177.17 r270 bottom
C228 "100n" CC1005-0402 -200,1400 r90 bottom
C229 "100n" CC1005-0402 -12.5,-775 r270 bottom
C230 "470n" FP-CL03-IPC_B -39.37,-177.17 r90 bottom
C231 "470n" FP-CL03-IPC_B -39.37,-59.06 r270 bottom
C232 "470n" FP-CL03-IPC_B -39.37,177.17 r90 bottom
C233 "470n" FP-CL03-IPC_B -59.06,-118.11 r180 bottom
C234 "470n" FP-CL03-IPC_B -59.06,118.11 r0 bottom
C235 "470n" FP-CL03-IPC_B -78.74,295.28 r270 bottom
C236 "100n" CC1005-0402 -100,975 r0 bottom
C237 "1.0u" CC1608-0603 -112.2,-78.74 r0 bottom
C238 "4.7u" CC1608-0603 -112.2,0 r0 bottom
C239 "4.7u" CC1608-0603 -114.17,78.74 r0 bottom
C240 "4.7u" CC1608-0603 -118.11,-196.85 r0 bottom
C241 "10u" CC2013-0805 -100,850 r270 bottom
C242 "10u" CC2013-0805 -200,1546.74 r270 bottom
C243 "470n" FP-CL03-IPC_B -137.8,-157.48 r180 bottom
C244 "470n" FP-CL03-IPC_B -137.8,-39.37 r0 bottom
C245 "470n" FP-CL03-IPC_B -137.8,39.37 r0 bottom
C246 "470n" FP-CL03-IPC_B -137.8,118.11 r0 bottom
C247 "470n" FP-CL03-IPC_B -157.48,295.28 r270 bottom
C248 "1.0n" CC1005-0402 -100,1337.5 r0 bottom
C249 "4.7u" CC1608-0603 -531.5,-295.28 r90 top
C250 "470n" FP-CL03-IPC_B -177.17,-236.22 r0 bottom
C251 "4.7u" CC1608-0603 -196.85,0 r270 bottom
C252 "4.7u" CC1608-0603 -196.85,137.8 r270 bottom
C253 "470n" FP-CL03-IPC_B -236.22,-59.06 r90 bottom
C254 "4.7u" CC1608-0603 -236.22,-216.54 r90 bottom
C255 "4.7u" CC1608-0603 -236.22,275.59 r90 bottom
C256 "100n" CC1005-0402 -293.75,-762.5 r180 bottom
C257 "470n" FP-CL03-IPC_B -137.8,-334.65 r315 bottom
C258 "10u" CC2013-0805 -447.5,-1305 r90 bottom
C259 "4.7u" CC1608-0603 -314.96,0 r0 bottom
C260 "470n" FP-CL03-IPC_B -295.28,374.02 r225 bottom
C261 "470n" FP-CL03-IPC_B -295.28,-334.65 r45 bottom
C262 "100n" CC2013-0805 -295.28,-216.54 r270 bottom
C263 "470n" FP-CL03-IPC_B -314.96,177.17 r90 bottom
C264 "1.0n" CC1005-0402 -468.75,-1487.5 r90 bottom
C265 "4.7u" CC1608-0603 -314.96,275.59 r90 bottom
C266 "470n" FP-CL03-IPC_B -334.65,59.06 r135 bottom
C267 "470n" FP-CL03-IPC_B -354.33,-295.28 r270 bottom
C268 "470n" FP-CL03-IPC_B -354.33,-98.43 r90 bottom
C269 "100n" CC1005-0402 -354.33,-216.54 r270 bottom
C270 "1.0u" CC1608-0603 -395.67,-295.28 r270 bottom
C271 "47u" CC3216-1206 -511.81,-314.96 r90 bottom
C272 "47u" CC3216-1206 -511.82,236.22 r270 bottom
C273 "220n" CC1005-0402 -550,-1350 r90 bottom
C274 "100n" CC1005-0402 -551.18,49.21 r90 bottom
C275 "100n" CC1005-0402 -551.18,-78.74 r90 bottom
C276 "220n" CC1005-0402 -587.5,-1350 r90 bottom
C277 "220n" CC1005-0402 -637.5,-1350 r90 bottom
C278 "220n" CC1005-0402 -675,-1350 r90 bottom
C279 "220n" CC1005-0402 -725,-1350 r90 bottom
C280 "220n" CC1005-0402 -762.5,-1350 r90 bottom
C281 "220n" CC1005-0402 -812.5,-1350 r90 bottom
C282 "100n" CC1005-0402 -812.5,-206.4 r270 bottom
C283 "220n" CC1005-0402 -850,-1350 r90 bottom
C284 "10n" CC1005-0402 -900,-1350 r90 bottom
C285 "10n" CC1005-0402 -937.48,-16.3 r0 bottom
C286 "10n" CC1005-0402 -937.5,-1350 r90 bottom
C287 "100n" CC1005-0402 -1137.5,-1350 r90 bottom
C288A "10u" CC1005-0402 -1600,1487.5 r180 bottom (schematic designator C288)
C288B "10u" CC1005-0402 -1600,1037.5 r180 bottom (schematic designator C288)
C288C "10u" CC1005-0402 -1600,587.5 r180 bottom (schematic designator C288)
C288D "10u" CC1005-0402 -1600,137.5 r180 bottom (schematic designator C288)
C288E "10u" CC1005-0402 -1600,-312.5 r180 bottom (schematic designator C288)
C288F "10u" CC1005-0402 -1600,-762.5 r180 bottom (schematic designator C288)
C288G "10u" CC1005-0402 -1600,-1212.5 r180 bottom (schematic designator C288)
C288H "10u" CC1005-0402 -1600,-1662.5 r180 bottom (schematic designator C288)
C289A "10u" CC1005-0402 -1600,1812.5 r180 bottom (schematic designator C289)
C289B "10u" CC1005-0402 -1600,1362.5 r180 bottom (schematic designator C289)
C289C "10u" CC1005-0402 -1600,912.5 r180 bottom (schematic designator C289)
C289D "10u" CC1005-0402 -1600,462.5 r180 bottom (schematic designator C289)
C289E "10u" CC1005-0402 -1600,12.5 r180 bottom (schematic designator C289)
C289F "10u" CC1005-0402 -1600,-437.5 r180 bottom (schematic designator C289)
C289G "10u" CC1005-0402 -1600,-887.5 r180 bottom (schematic designator C289)
C289H "10u" CC1005-0402 -1600,-1337.5 r180 bottom (schematic designator C289)
C304A "10u" CC1005-0402 -1706.89,1437.5 r180 bottom (schematic designator C304)
C304B "10u" CC1005-0402 -1706.89,987.5 r180 bottom (schematic designator C304)
C304C "10u" CC1005-0402 -1706.89,537.5 r180 bottom (schematic designator C304)
C304D "10u" CC1005-0402 -1706.89,87.5 r180 bottom (schematic designator C304)
C304E "10u" CC1005-0402 -1706.89,-362.5 r180 bottom (schematic designator C304)
C304F "10u" CC1005-0402 -1706.89,-812.5 r180 bottom (schematic designator C304)
C304G "10u" CC1005-0402 -1706.89,-1262.5 r180 bottom (schematic designator C304)
C304H "10u" CC1005-0402 -1706.89,-1712.5 r180 bottom (schematic designator C304)
C312A "10u" CC1005-0402 -1825,1437.5 r0 bottom (schematic designator C312)
C312B "10u" CC1005-0402 -1825,987.5 r0 bottom (schematic designator C312)
C312C "10u" CC1005-0402 -1825,537.5 r0 bottom (schematic designator C312)
C312D "10u" CC1005-0402 -1825,87.5 r0 bottom (schematic designator C312)
C312E "10u" CC1005-0402 -1825,-362.5 r0 bottom (schematic designator C312)
C312F "10u" CC1005-0402 -1825,-812.5 r0 bottom (schematic designator C312)
C312G "10u" CC1005-0402 -1825,-1262.5 r0 bottom (schematic designator C312)
C312H "10u" CC1005-0402 -1825,-1712.5 r0 bottom (schematic designator C312)
C320A "100n" CC0603-0201 -1795.47,1804.62 r270 bottom (schematic designator C320)
C320B "100n" CC0603-0201 -1795.47,1354.62 r270 bottom (schematic designator C320)
C320C "100n" CC0603-0201 -1795.47,904.62 r270 bottom (schematic designator C320)
C320D "100n" CC0603-0201 -1795.47,454.62 r270 bottom (schematic designator C320)
C320E "100n" CC0603-0201 -1795.47,4.62 r270 bottom (schematic designator C320)
C320F "100n" CC0603-0201 -1795.47,-445.38 r270 bottom (schematic designator C320)
C320G "100n" CC0603-0201 -1795.47,-895.38 r270 bottom (schematic designator C320)
C320H "100n" CC0603-0201 -1795.47,-1345.38 r270 bottom (schematic designator C320)
C328A "100n" CC0603-0201 -1874.21,1804.62 r270 bottom (schematic designator C328)
C328B "100n" CC0603-0201 -1874.21,1354.62 r270 bottom (schematic designator C328)
C328C "100n" CC0603-0201 -1874.21,904.62 r270 bottom (schematic designator C328)
C328D "100n" CC0603-0201 -1874.21,454.62 r270 bottom (schematic designator C328)
C328E "100n" CC0603-0201 -1874.21,4.62 r270 bottom (schematic designator C328)
C328F "100n" CC0603-0201 -1874.21,-445.38 r270 bottom (schematic designator C328)
C328G "100n" CC0603-0201 -1874.21,-895.38 r270 bottom (schematic designator C328)
C328H "100n" CC0603-0201 -1874.21,-1345.38 r270 bottom (schematic designator C328)
C336A "100n" CC0603-0201 -1893.9,1804.62 r270 bottom (schematic designator C336)
C336B "100n" CC0603-0201 -1893.9,1354.62 r270 bottom (schematic designator C336)
C336C "100n" CC0603-0201 -1893.9,904.62 r270 bottom (schematic designator C336)
C336D "100n" CC0603-0201 -1893.9,454.62 r270 bottom (schematic designator C336)
C336E "100n" CC0603-0201 -1893.9,4.62 r270 bottom (schematic designator C336)
C336F "100n" CC0603-0201 -1893.9,-445.38 r270 bottom (schematic designator C336)
C336G "100n" CC0603-0201 -1893.9,-895.38 r270 bottom (schematic designator C336)
C336H "100n" CC0603-0201 -1893.9,-1345.38 r270 bottom (schematic designator C336)
C344A "1.0u" CC1005-0402 -1943.11,1437.5 r0 bottom (schematic designator C344)
C344B "1.0u" CC1005-0402 -1943.11,987.5 r0 bottom (schematic designator C344)
C344C "1.0u" CC1005-0402 -1943.11,537.5 r0 bottom (schematic designator C344)
C344D "1.0u" CC1005-0402 -1943.11,87.5 r0 bottom (schematic designator C344)
C344E "1.0u" CC1005-0402 -1943.11,-362.5 r0 bottom (schematic designator C344)
C344F "1.0u" CC1005-0402 -1943.11,-812.5 r0 bottom (schematic designator C344)
C344G "1.0u" CC1005-0402 -1943.11,-1262.5 r0 bottom (schematic designator C344)
C344H "1.0u" CC1005-0402 -1943.11,-1712.5 r0 bottom (schematic designator C344)
C352A "100n" CC0603-0201 -1913.58,1804.62 r270 bottom (schematic designator C352)
C352B "100n" CC0603-0201 -1913.58,1354.62 r270 bottom (schematic designator C352)
C352C "100n" CC0603-0201 -1913.58,904.62 r270 bottom (schematic designator C352)
C352D "100n" CC0603-0201 -1913.58,454.62 r270 bottom (schematic designator C352)
C352E "100n" CC0603-0201 -1913.58,4.62 r270 bottom (schematic designator C352)
C352F "100n" CC0603-0201 -1913.58,-445.38 r270 bottom (schematic designator C352)
C352G "100n" CC0603-0201 -1913.58,-895.38 r270 bottom (schematic designator C352)
C352H "100n" CC0603-0201 -1913.58,-1345.38 r270 bottom (schematic designator C352)
C360A "2.2u" CC0603-0201 -1933.27,1495.38 r90 bottom (schematic designator C360)
C360B "2.2u" CC0603-0201 -1933.27,1045.38 r90 bottom (schematic designator C360)
C360C "2.2u" CC0603-0201 -1933.27,595.38 r90 bottom (schematic designator C360)
C360D "2.2u" CC0603-0201 -1933.27,145.38 r90 bottom (schematic designator C360)
C360E "2.2u" CC0603-0201 -1933.27,-304.62 r90 bottom (schematic designator C360)
C360F "2.2u" CC0603-0201 -1933.27,-754.62 r90 bottom (schematic designator C360)
C360G "2.2u" CC0603-0201 -1933.27,-1204.62 r90 bottom (schematic designator C360)
C360H "2.2u" CC0603-0201 -1933.27,-1654.62 r90 bottom (schematic designator C360)
C361A "1.0u" CC0603-0201 -1933.27,1804.62 r270 bottom value=1u (schematic designator C361)
C361B "1.0u" CC0603-0201 -1933.27,1354.62 r270 bottom value=1u (schematic designator C361)
C361C "1.0u" CC0603-0201 -1933.27,904.62 r270 bottom value=1u (schematic designator C361)
C361D "1.0u" CC0603-0201 -1933.27,454.62 r270 bottom value=1u (schematic designator C361)
C361E "1.0u" CC0603-0201 -1933.27,4.62 r270 bottom value=1u (schematic designator C361)
C361F "1.0u" CC0603-0201 -1933.27,-445.38 r270 bottom value=1u (schematic designator C361)
C361G "1.0u" CC0603-0201 -1933.27,-895.38 r270 bottom value=1u (schematic designator C361)
C361H "1.0u" CC0603-0201 -1933.27,-1345.38 r270 bottom value=1u (schematic designator C361)
C383A "1.0u" CC0603-0201 -1979.62,1640.16 r180 bottom value=1u (schematic designator C383)
C383B "1.0u" CC0603-0201 -1979.62,1190.16 r180 bottom value=1u (schematic designator C383)
C383C "1.0u" CC0603-0201 -1979.62,740.16 r180 bottom value=1u (schematic designator C383)
C383D "1.0u" CC0603-0201 -1979.62,290.16 r180 bottom value=1u (schematic designator C383)
C383E "1.0u" CC0603-0201 -1979.62,-159.84 r180 bottom value=1u (schematic designator C383)
C383F "1.0u" CC0603-0201 -1979.62,-609.84 r180 bottom value=1u (schematic designator C383)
